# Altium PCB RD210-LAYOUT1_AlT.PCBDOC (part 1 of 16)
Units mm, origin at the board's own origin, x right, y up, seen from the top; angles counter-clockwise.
Board outline 330 x 300 mm, 6 copper layers (TOP, Mid-Layer 1, Mid-Layer 2, Mid-Layer 3, Mid-Layer 4, BOTTOM), stack 1.422 mm thick; 981 components, 463 nets, 2326 pads, 12534 vias.
Unrouted connection lines stored in the file: 6.
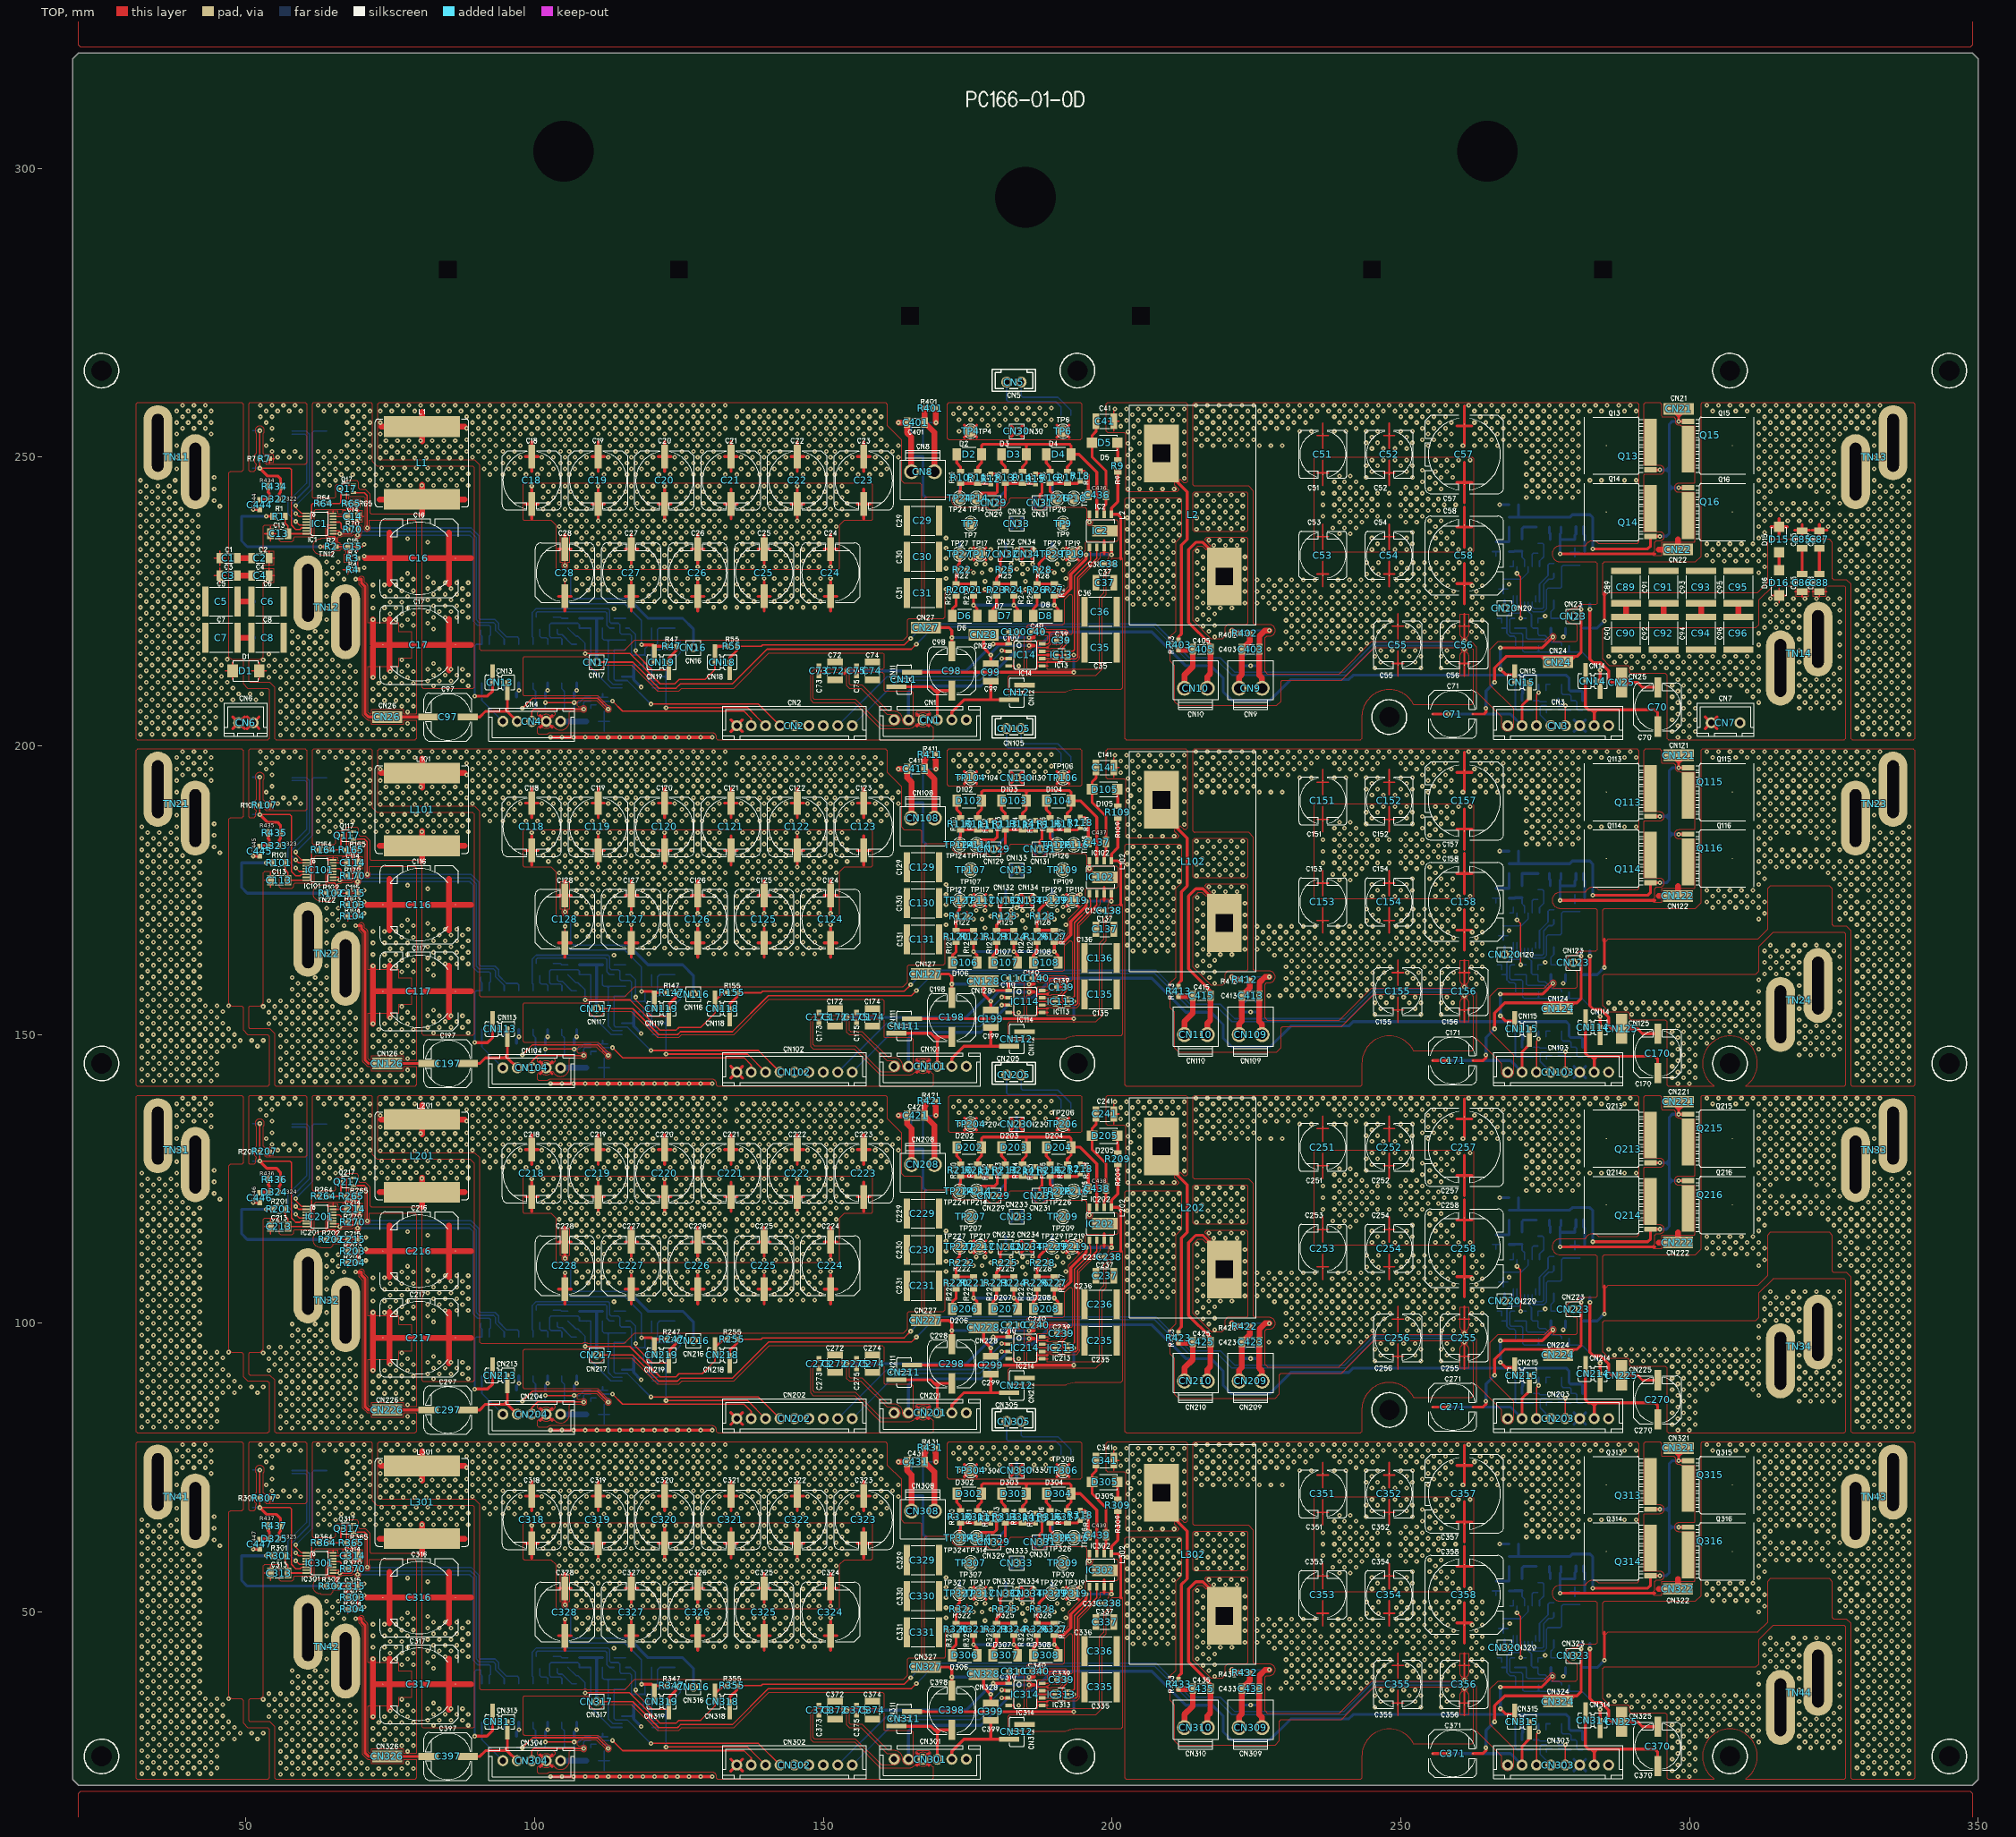
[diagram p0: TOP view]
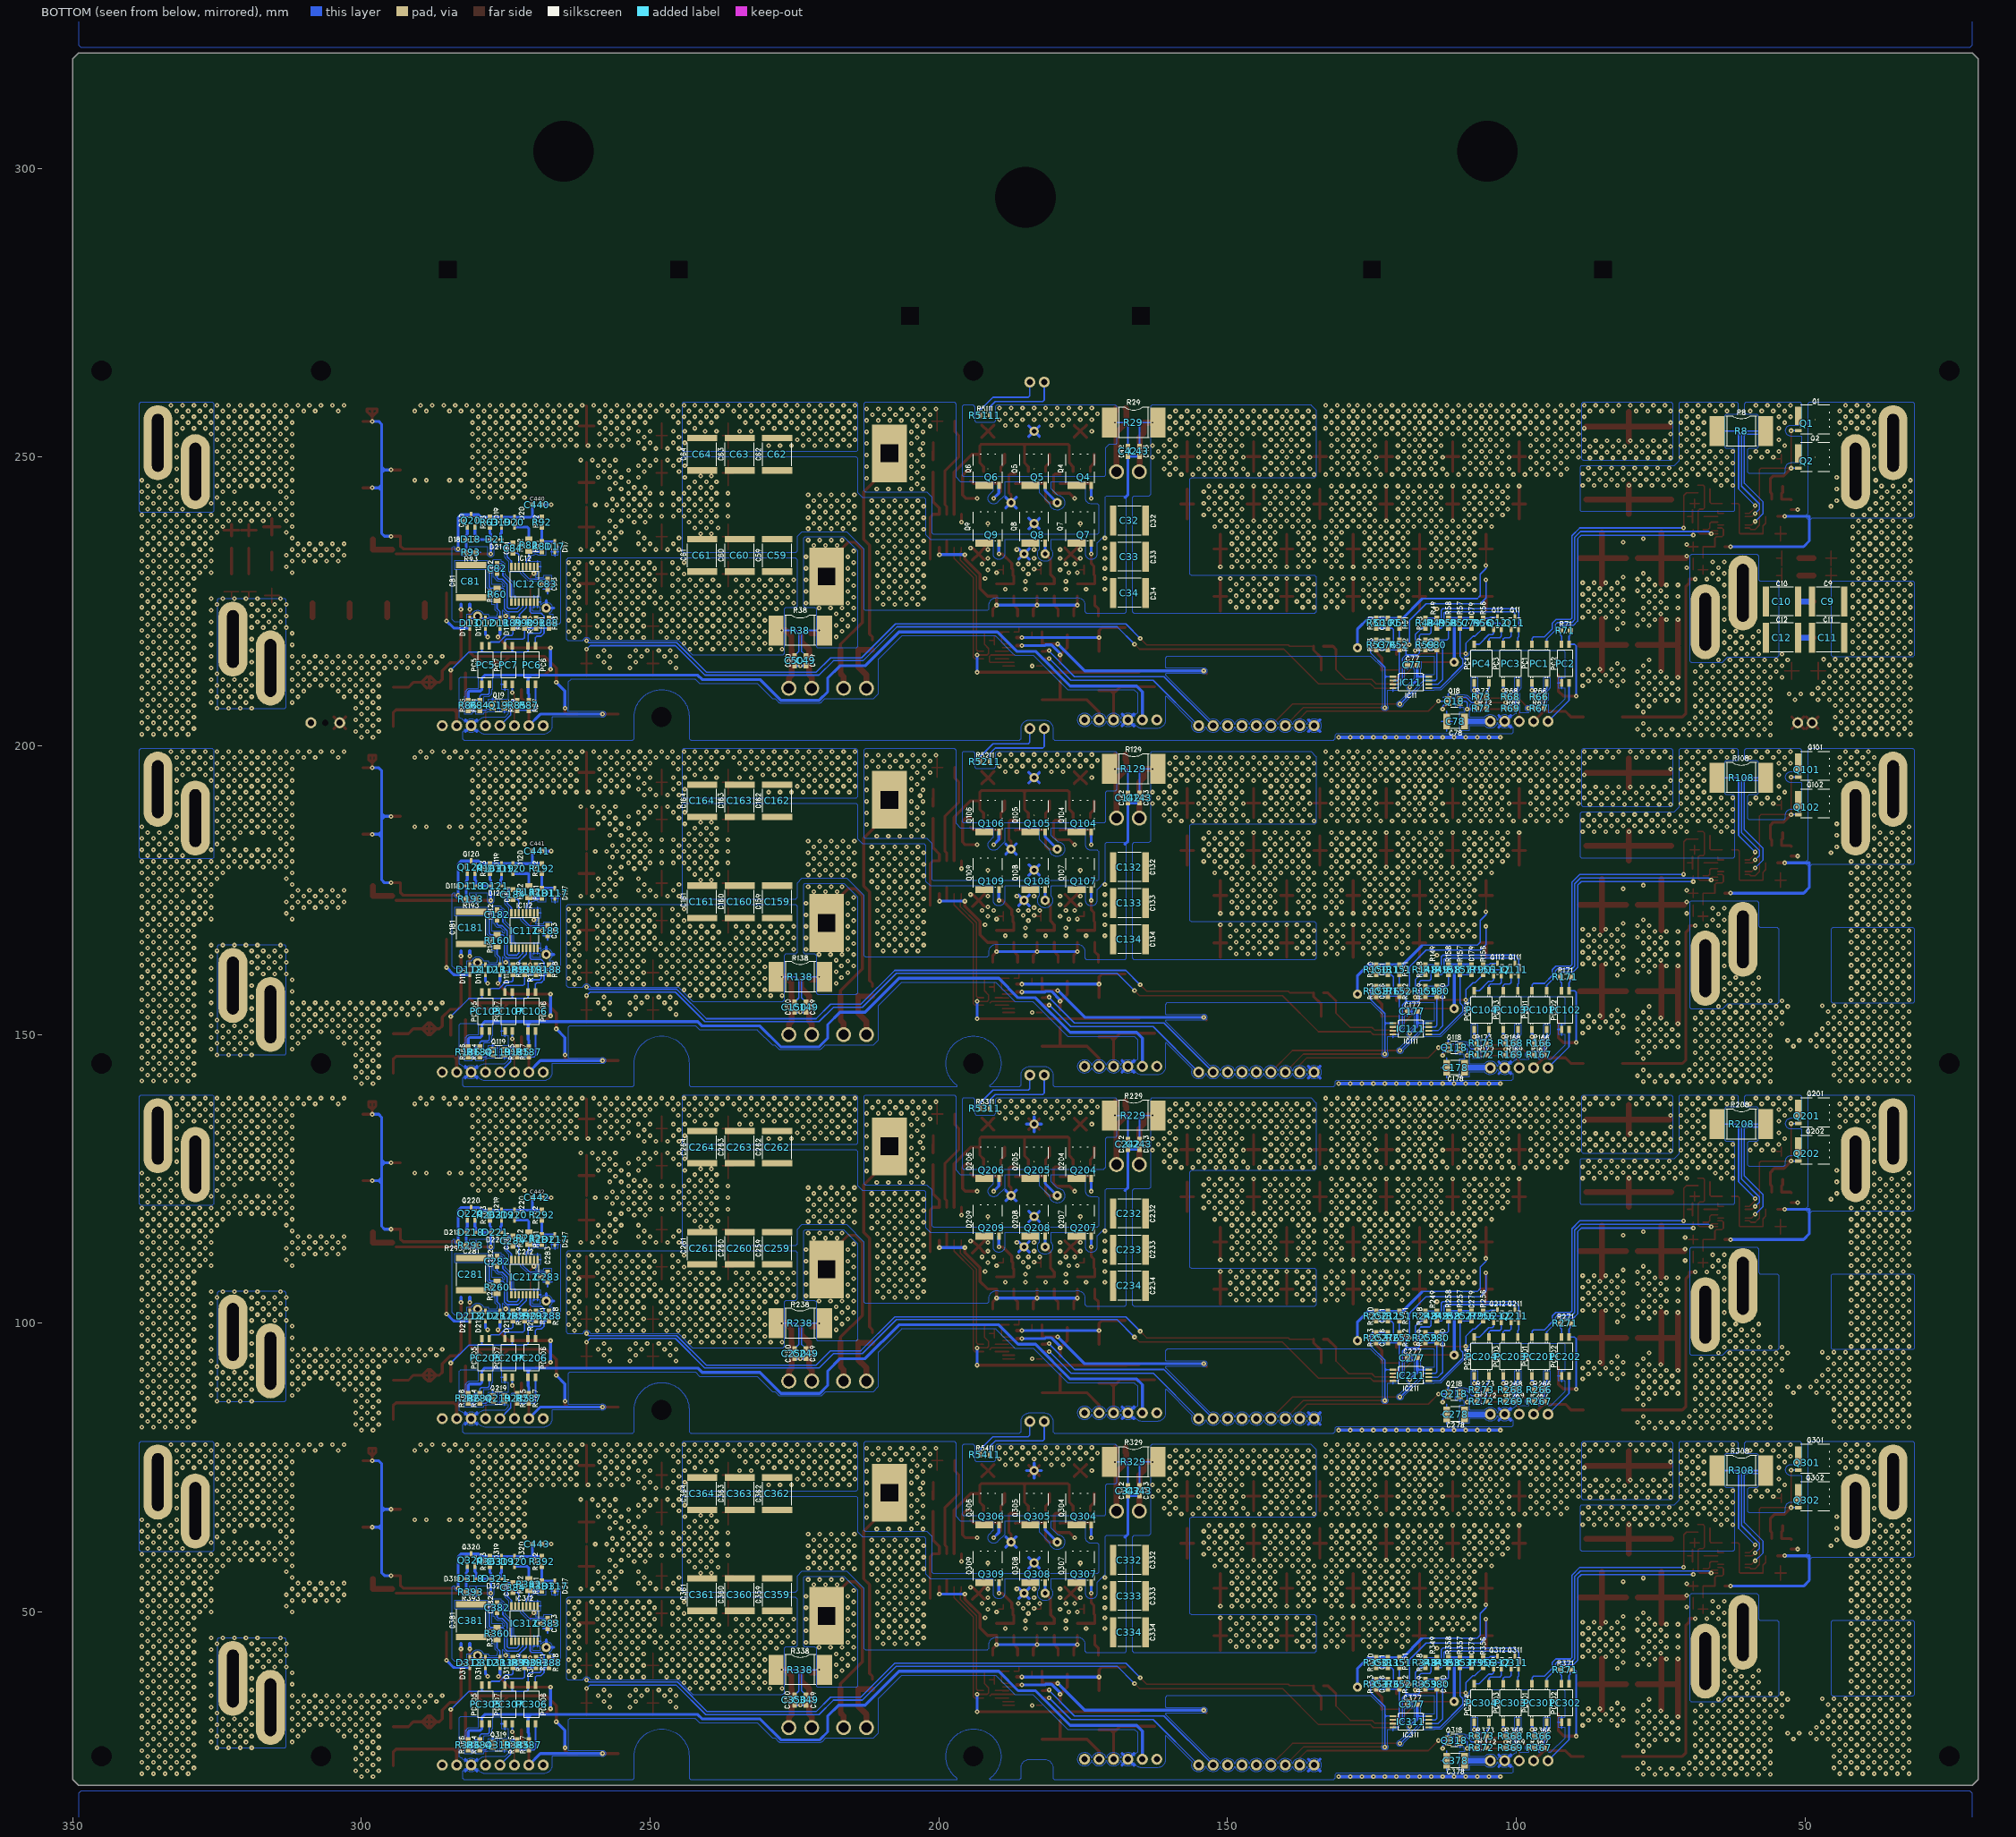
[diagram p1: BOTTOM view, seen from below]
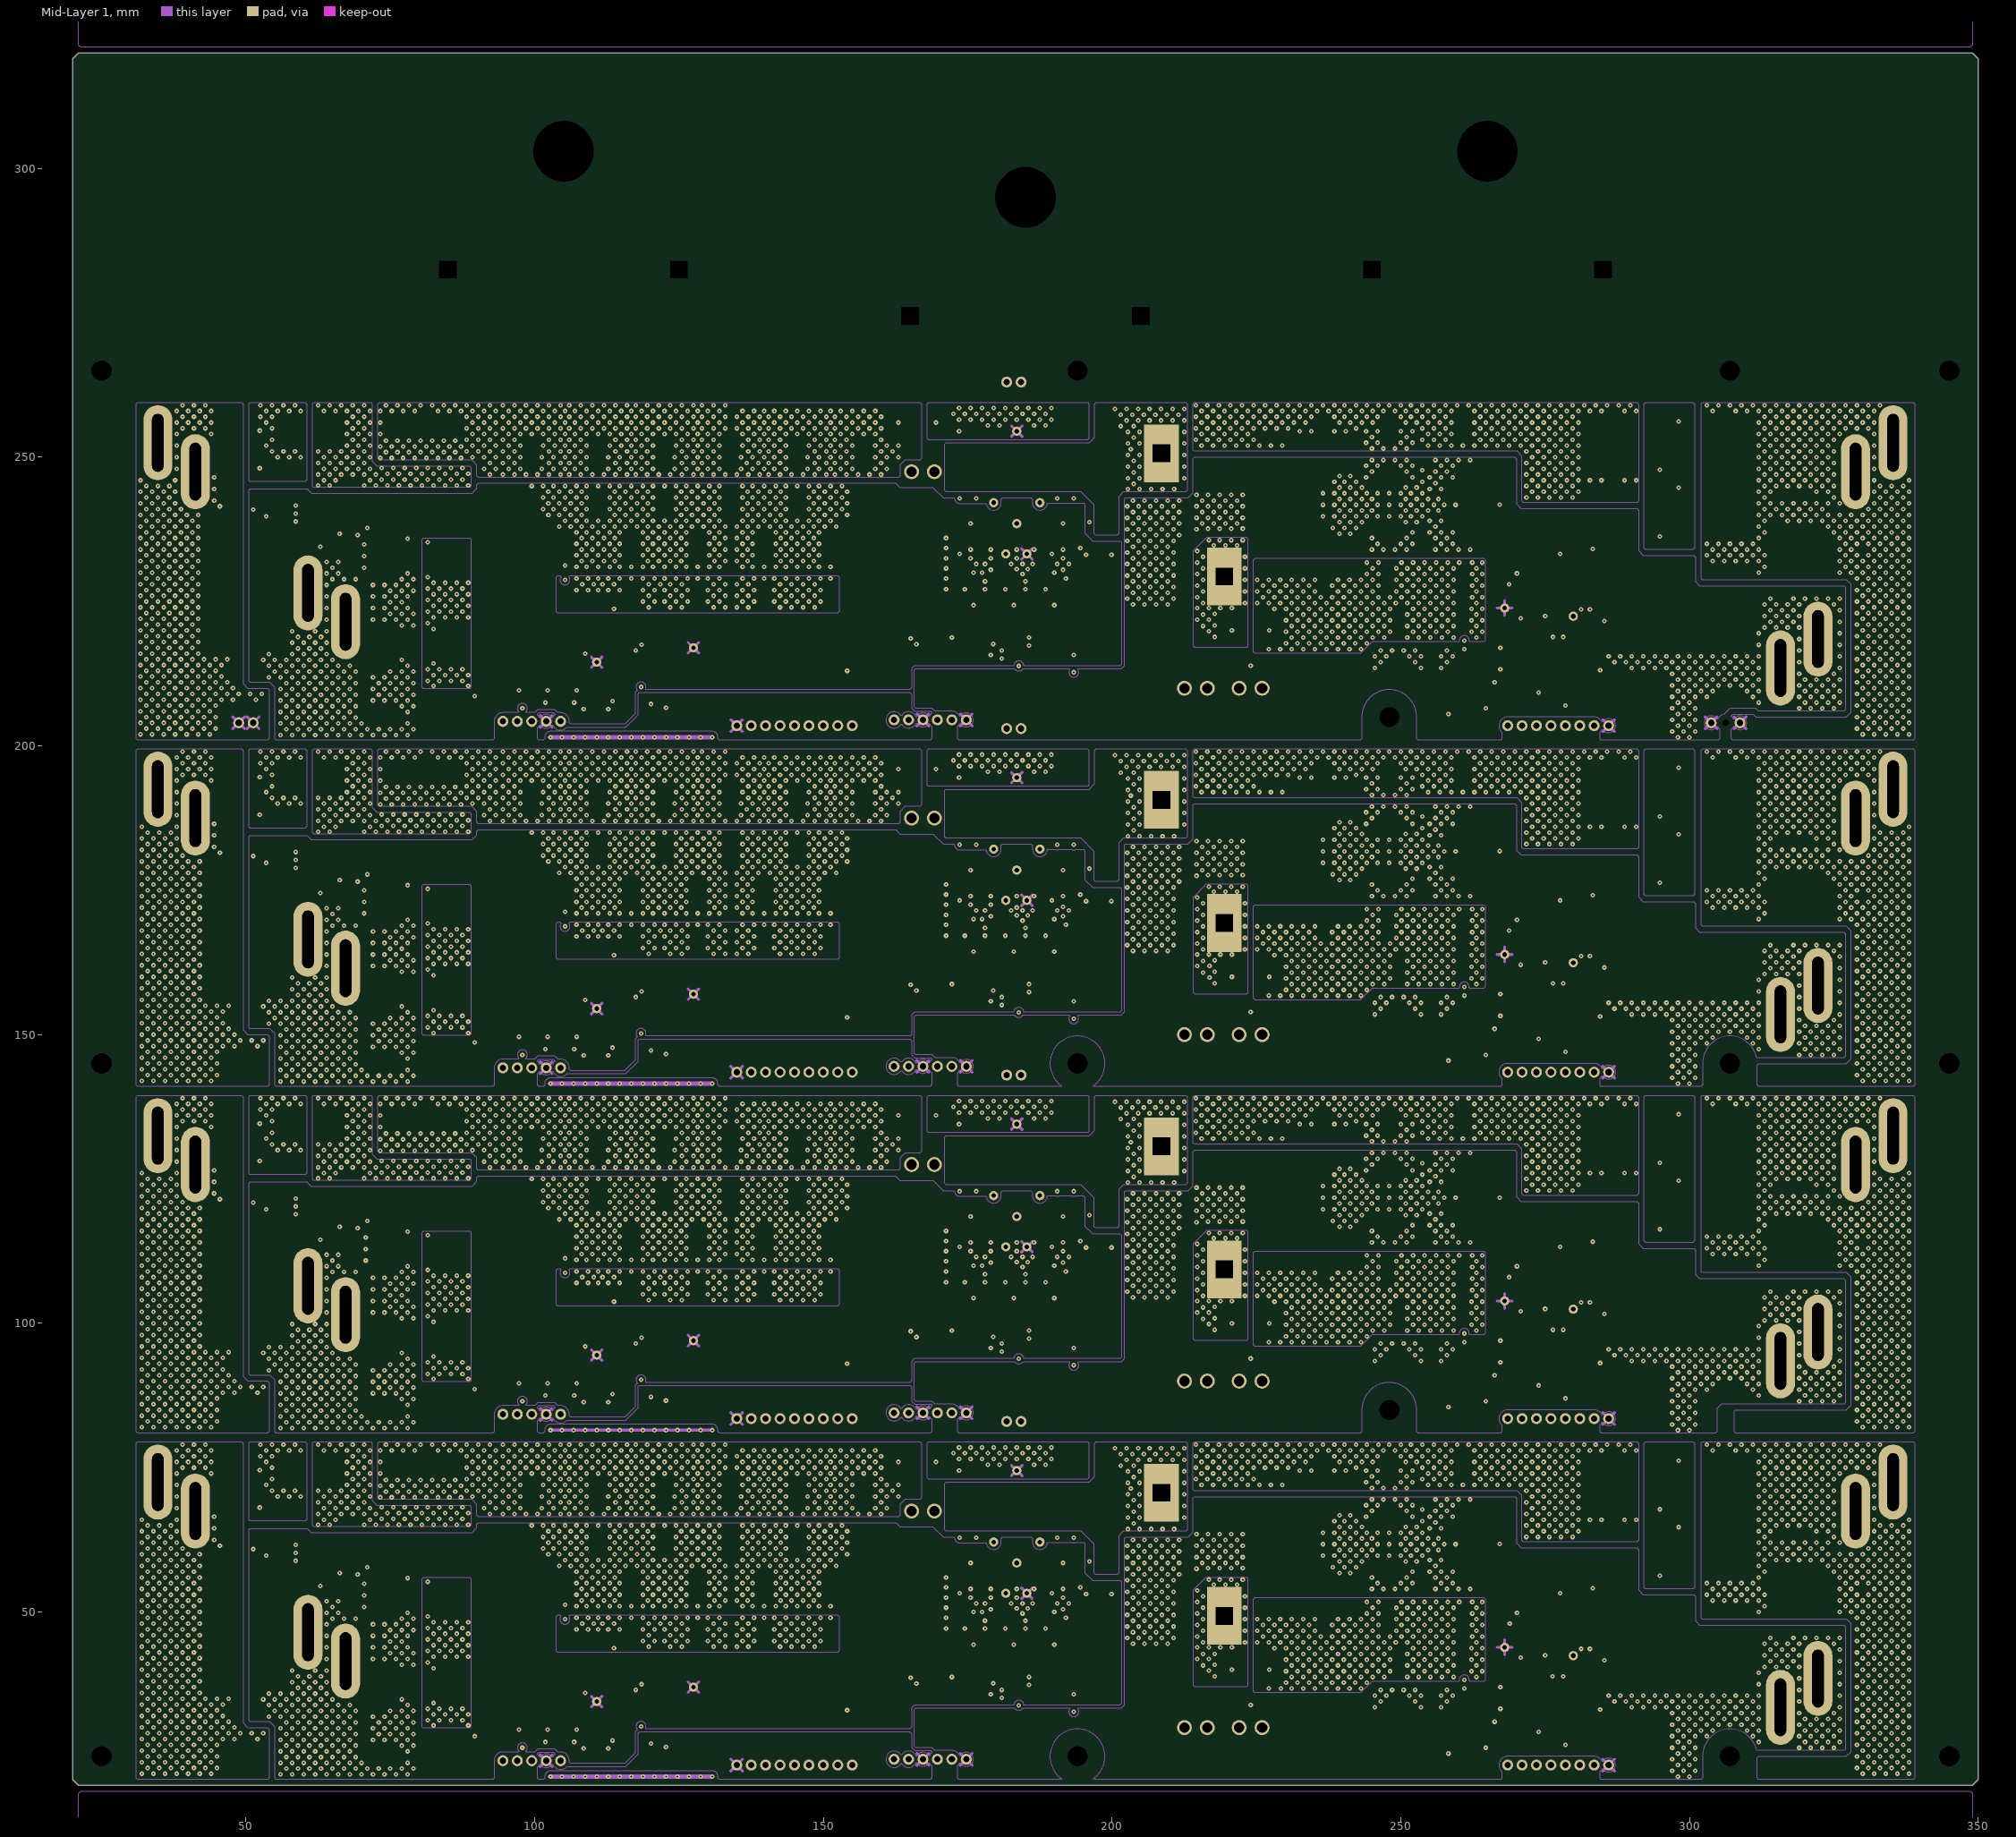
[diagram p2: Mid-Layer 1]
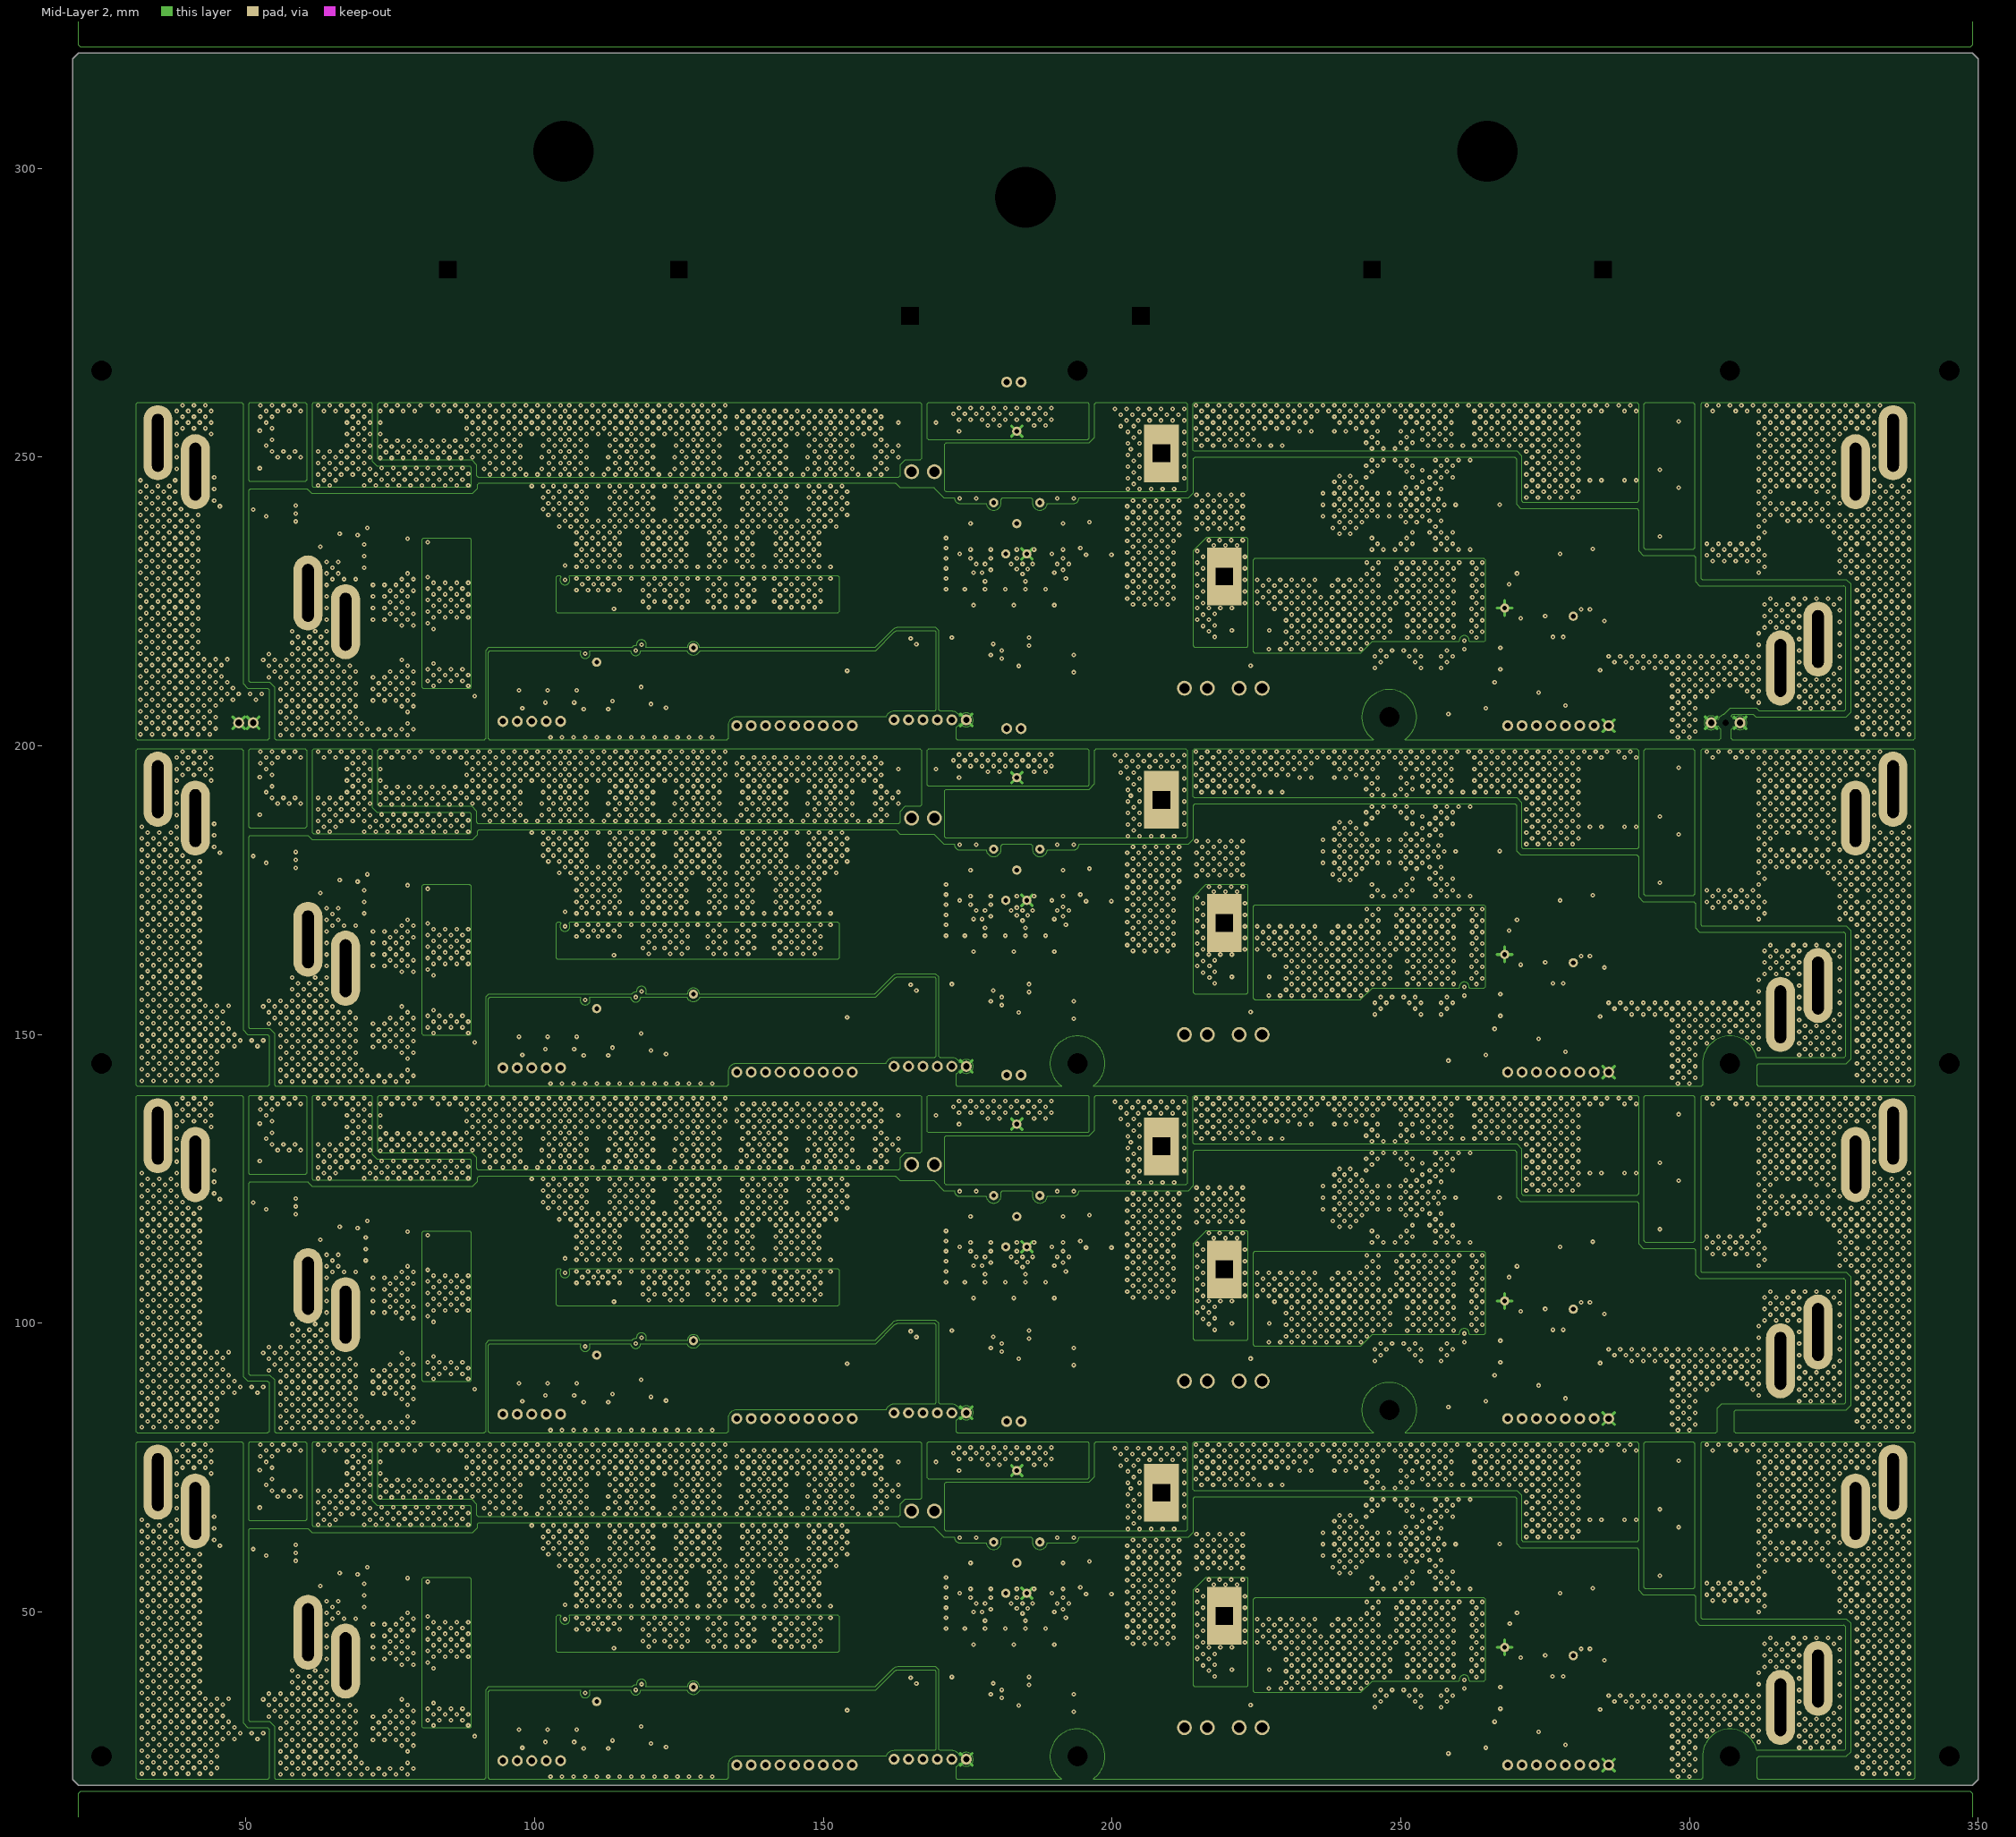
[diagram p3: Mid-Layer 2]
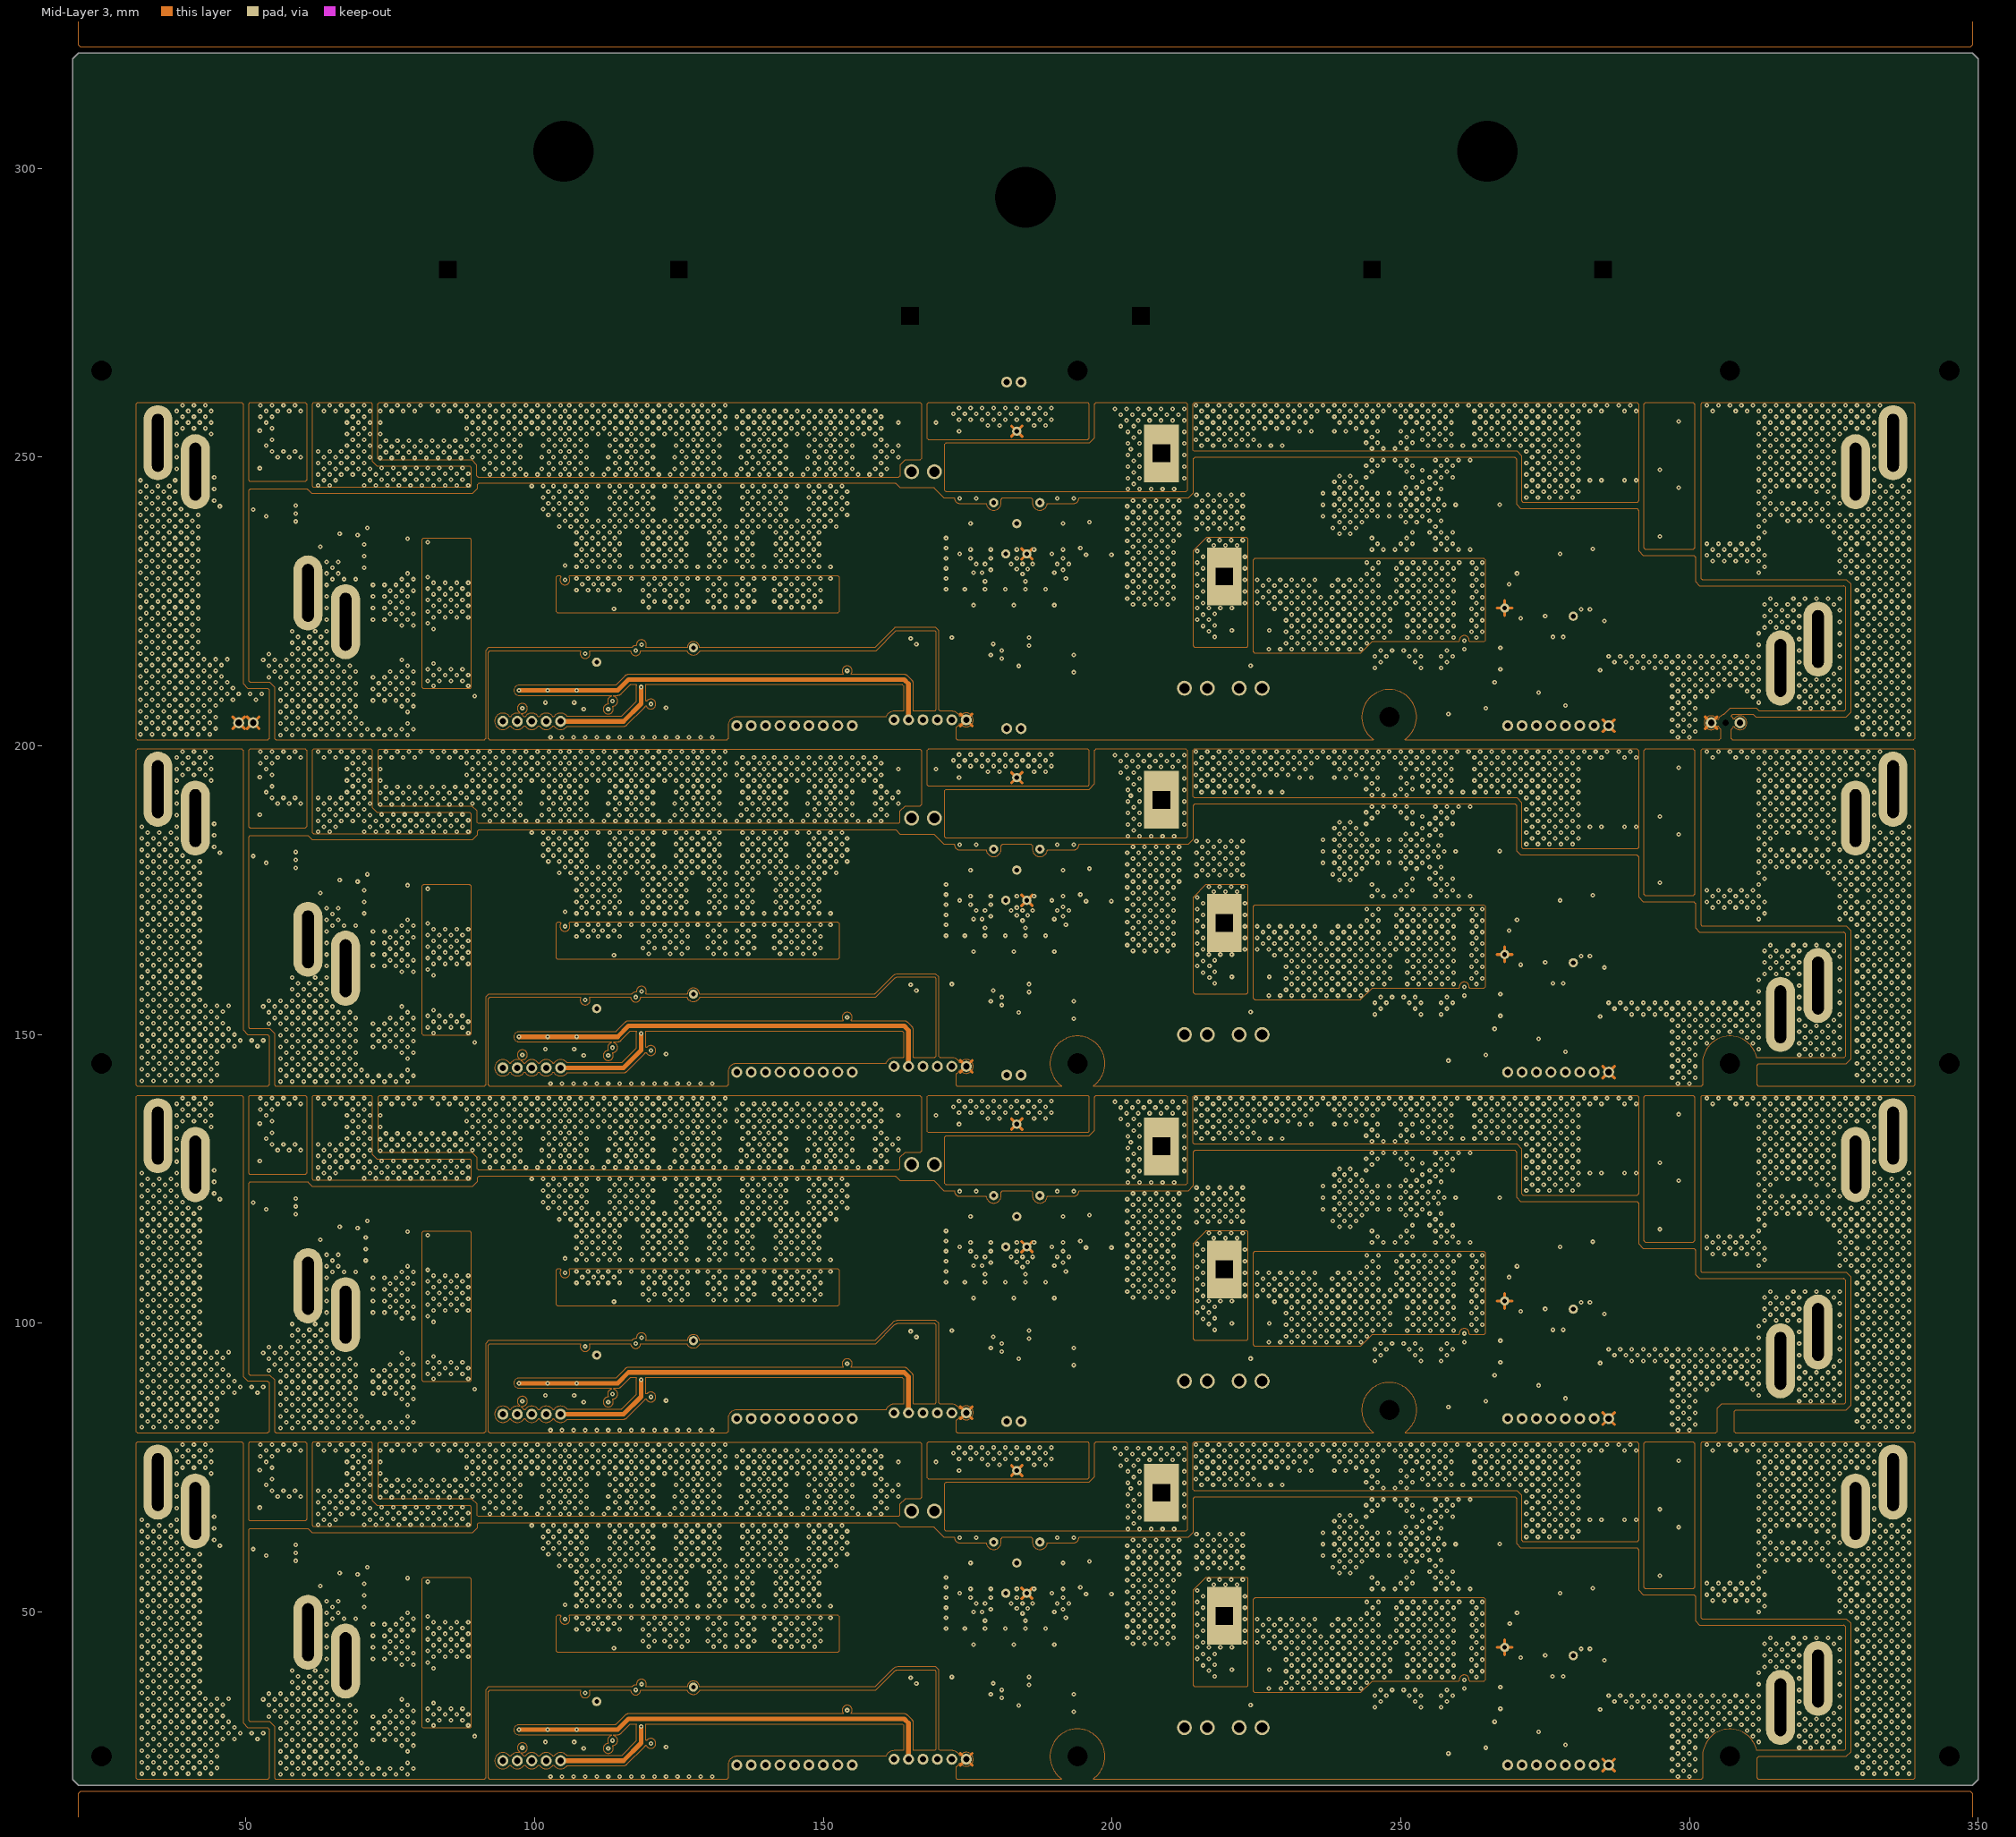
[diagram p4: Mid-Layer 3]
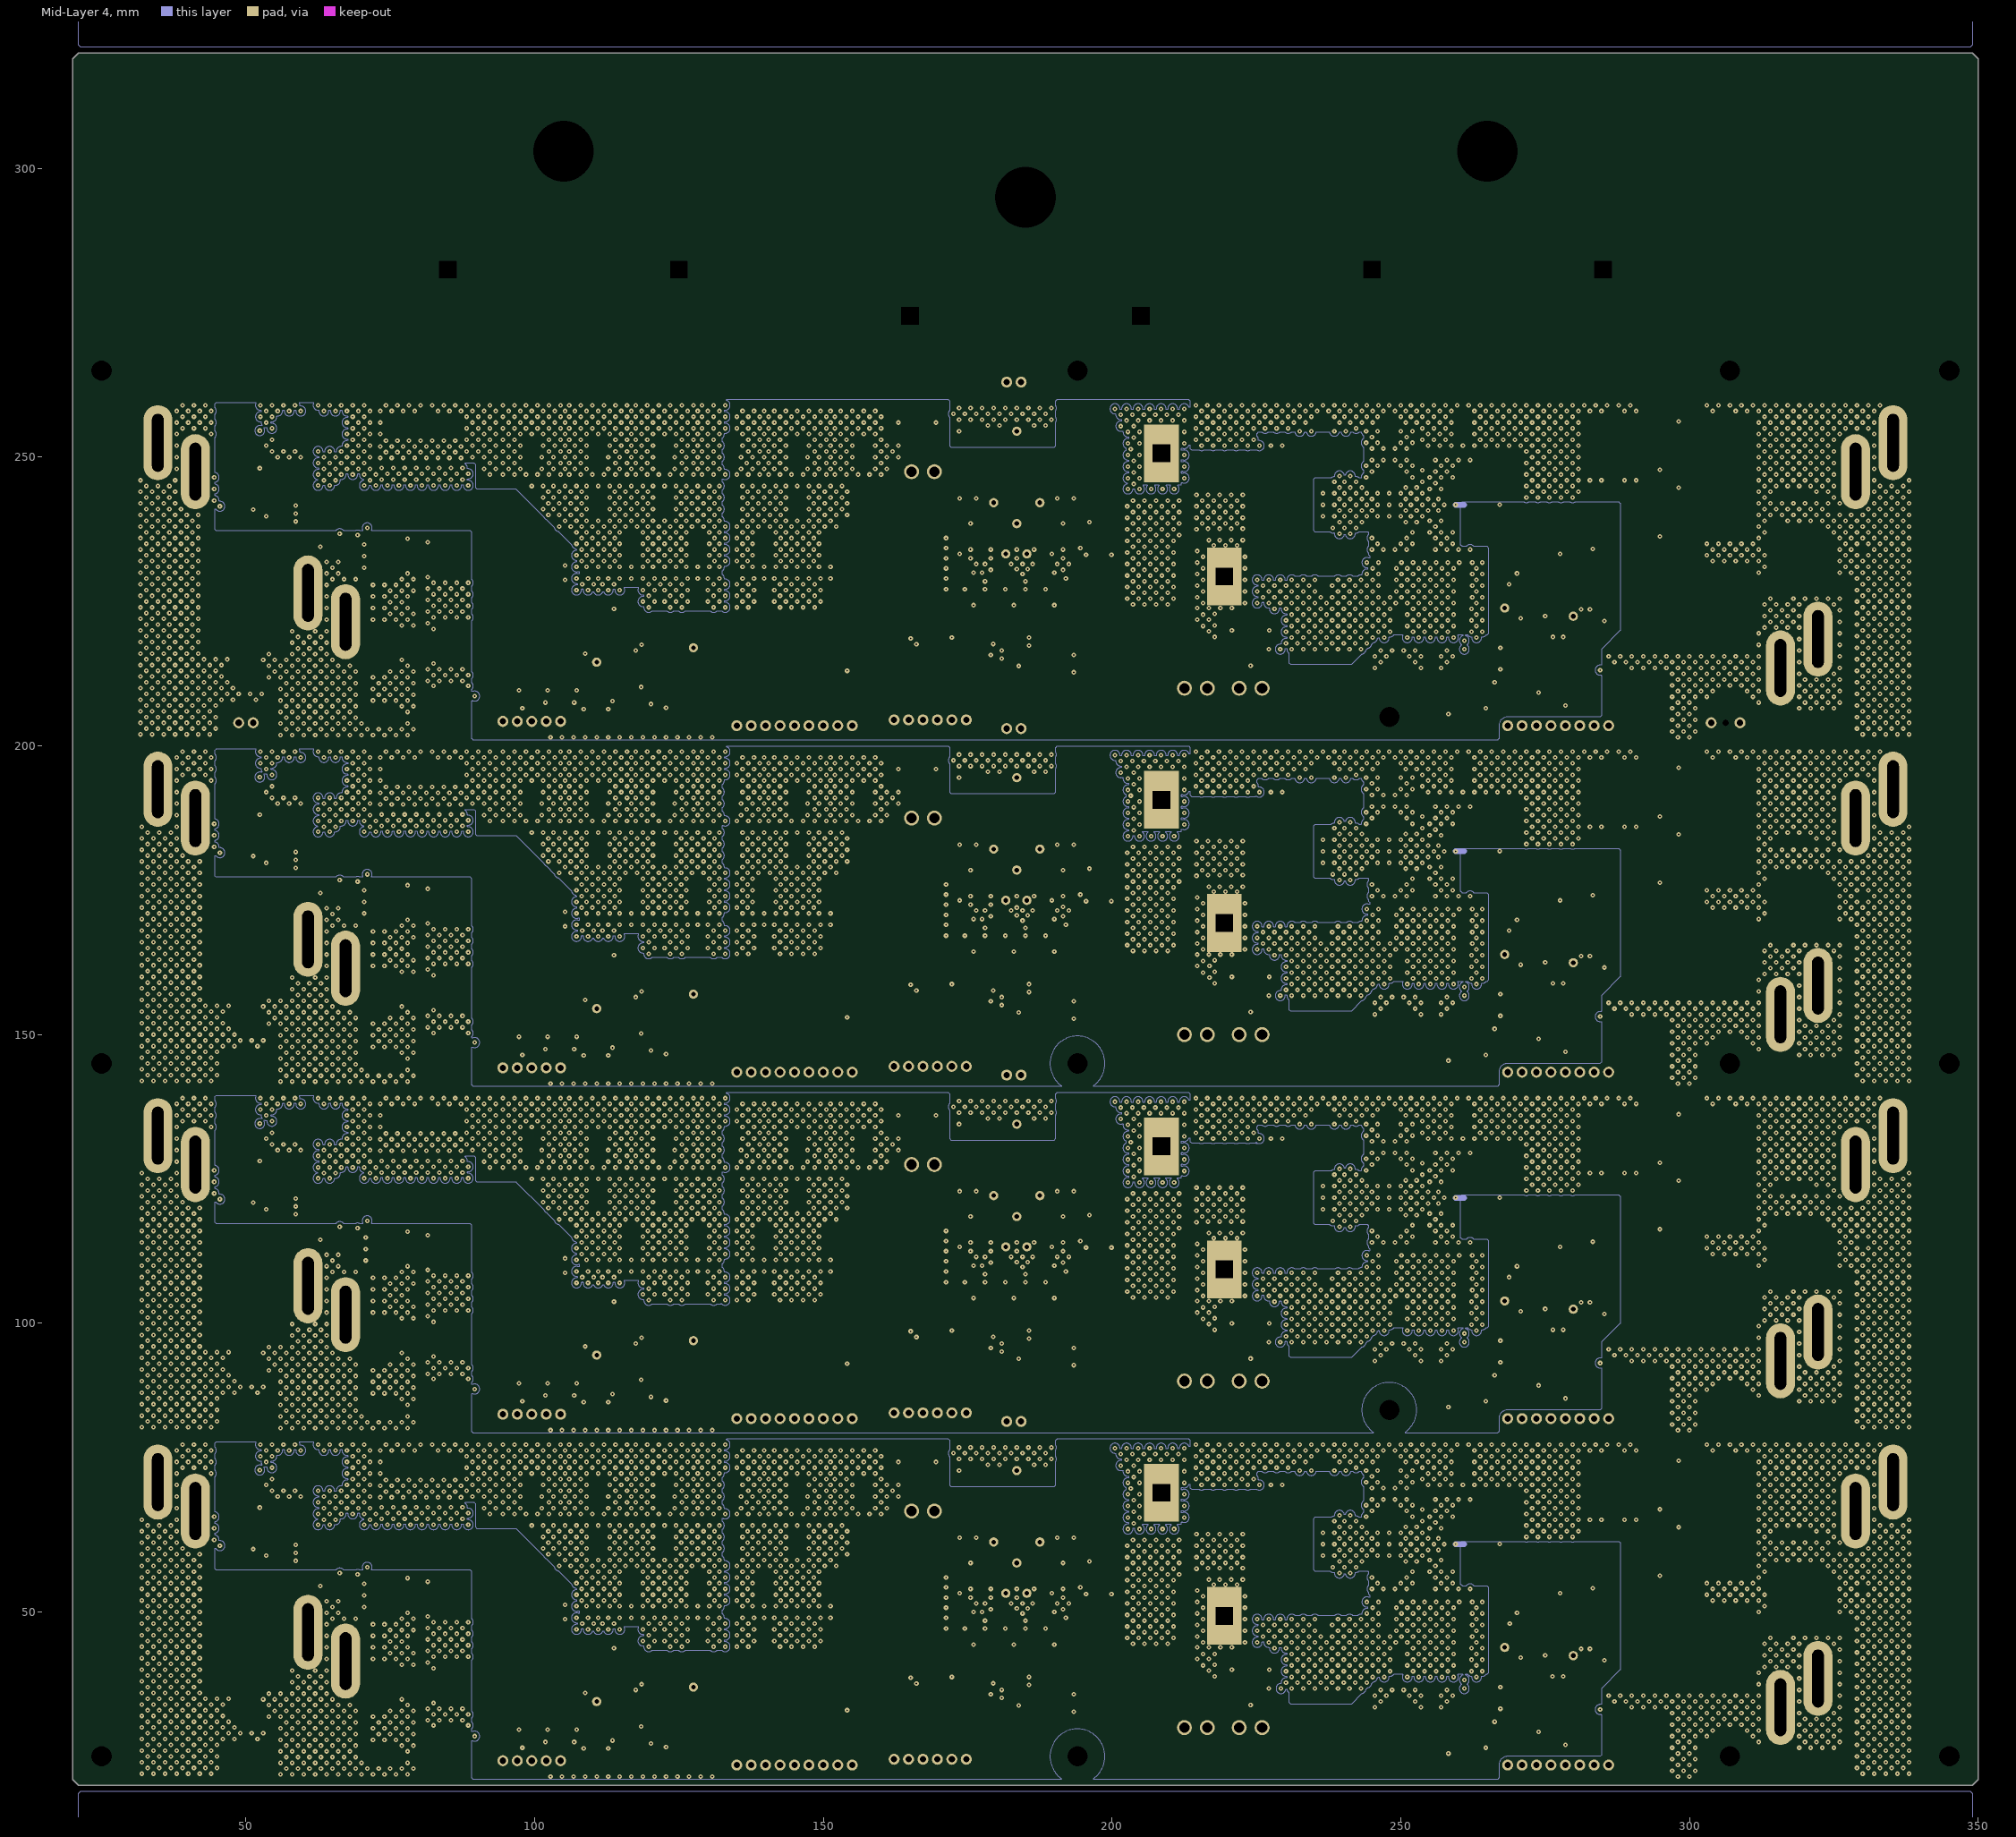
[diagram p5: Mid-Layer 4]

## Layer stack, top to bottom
Top Solder: solder mask 0.0102, Solder Resist, Dk 3.5
TOP: signal copper (thickness not stored)
Mid-Layer 1: signal copper 0.0356
Dielectric2: dielectric 0.32, FR-4, Dk 4.8
Mid-Layer 2: signal copper 0.0356
Dielectric3: dielectric 0.32, FR-4, Dk 4.8
Mid-Layer 3: signal copper 0.0356
Dielectric4: dielectric 0.32, FR-4, Dk 4.8
Mid-Layer 4: signal copper 0.0356
Dielectric5: dielectric 0.32, FR-4, Dk 4.8
BOTTOM: signal copper (thickness not stored)
Bottom Solder: solder mask 0.0102, Solder Resist, Dk 3.5

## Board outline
21,20 20,21 20,319 21,320 349,320 350,319 350,21 349,20

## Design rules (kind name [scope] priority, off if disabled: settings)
AssemblyTestPointUsage [All] p0: scope1count=1 scope1_0_kind=Board scope1_0_value=Board scope2count=1 scope2_0_kind=Board scope2_0_value=Board commentlength=0
AssemblyTestpoint [All] p0: scope1count=1 scope1_0_kind=Board scope1_0_value=Board scope2count=1 scope2_0_kind=Board scope2_0_value=Board commentlength=0
Clearance [All] p0: scope1count=1 scope1_0_kind=Board scope1_0_value=Board scope2count=1 scope2_0_kind=Board scope2_0_value=Board commentlength=0 gap=0.15
Clearance [All] p1: gap=0.15 ignorepadtopadclearanceinfootprint=TRUE except(0.3: Arc-Hole Track-Hole SMDPad-Hole THPad-Hole Via-Hole Fill-Hole Poly-Hole Region-Hole Text-Hole)
ComponentClearance [All] p0: scope1count=1 scope1_0_kind=Board scope1_0_value=Board scope2count=1 scope2_0_kind=Board scope2_0_value=Board commentlength=0 gap=0.254 collisioncheckmode=3
DiffPairsRouting [All] p0: scope1count=1 scope1_0_kind=Board scope1_0_value=Board scope2count=1 scope2_0_kind=Board scope2_0_value=Board commentlength=0
FabricationTestPointUsage [All] p0: scope1count=1 scope1_0_kind=Board scope1_0_value=Board scope2count=1 scope2_0_kind=Board scope2_0_value=Board commentlength=0 valid=0 allowmultiple=FALSE
FabricationTestpoint [All] p0: scope1count=1 scope1_0_kind=Board scope1_0_value=Board scope2count=1 scope2_0_kind=Board scope2_0_value=Board commentlength=0 side=3 testpointundercomponent=TRUE minsize=1.016 maxsize=2.54 preferedsize=1.524 minholesize=0 maxholesize=1.016 preferedholesize=0.813 testpointgrid=0.025
FanoutControl Fanout_BGA [All] p0 off: scope1count=1 scope1_0_kind=Board scope1_0_value=Board scope2count=1 scope2_0_kind=Board scope2_0_value=Board commentlength=69 // Protel DXP Scope 1 Expression Was: IsBGA   Fanout_BGA (Default Rule)
FanoutControl Fanout_LCC [All] p0 off: scope1count=1 scope1_0_kind=Board scope1_0_value=Board scope2count=1 scope2_0_kind=Board scope2_0_value=Board commentlength=69 // Protel DXP Scope 1 Expression Was: IsLCC   Fanout_LCC (Default Rule)
FanoutControl Fanout_SOIC [All] p0 off: scope1count=1 scope1_0_kind=Board scope1_0_value=Board scope2count=1 scope2_0_kind=Board scope2_0_value=Board commentlength=71 // Protel DXP Scope 1 Expression Was: IsSOIC   Fanout_SOIC (Default Rule)
FanoutControl Fanout_Small [All] p0 off: scope1count=1 scope1_0_kind=Board scope1_0_value=Board scope2count=1 scope2_0_kind=Board scope2_0_value=Board commentlength=84 // Protel DXP Scope 1 Expression Was: (CompPinCount < 5)   Fanout_Small (Default Rule)
FanoutControl Fanout_Default [All] p0: scope1count=1 scope1_0_kind=Board scope1_0_value=Board scope2count=1 scope2_0_kind=Board scope2_0_value=Board commentlength=30 // Fanout_Default (Default Rule)
Height [All] p0: scope1count=1 scope1_0_kind=Board scope1_0_value=Board scope2count=1 scope2_0_kind=Board scope2_0_value=Board commentlength=0
HoleSize [All] p0: scope1count=1 scope1_0_kind=Board scope1_0_value=Board scope2count=1 scope2_0_kind=Board scope2_0_value=Board commentlength=0 absolutevalues=TRUE maxlimit=100 minlimit=0.001 maxpercent=80.000 minpercent=20.000
HoleSize [All] p1: absolutevalues=TRUE maxlimit=100 minlimit=0.001 maxpercent=80.000 minpercent=20.000
HoleToHoleClearance [All] p0: scope1count=1 scope1_0_kind=Board scope1_0_value=Board scope2count=1 scope2_0_kind=Board scope2_0_value=Board commentlength=0
HoleToHoleClearance [All] p1: gap=0.4 allowstackedmicrovias=FALSE
LayerPairs [All] p0: scope1count=1 scope1_0_kind=Board scope1_0_value=Board scope2count=1 scope2_0_kind=Board scope2_0_value=Board commentlength=0 enforce=TRUE
MinimumSolderMaskSliver [All] p0: scope1count=1 scope1_0_kind=Board scope1_0_value=Board scope2count=1 scope2_0_kind=Board scope2_0_value=Board commentlength=0
MinimumSolderMaskSliver [All] p1: minsoldermaskwidth=0.1
NetAntennae [All] p0: scope1count=1 scope1_0_kind=Board scope1_0_value=Board scope2count=1 scope2_0_kind=Board scope2_0_value=Board commentlength=0
NetAntennae [All] p1: netantennaetolerance=100
PasteMaskExpansion [All] p0: scope1count=1 scope1_0_kind=Board scope1_0_value=Board scope2count=1 scope2_0_kind=Board scope2_0_value=Board commentlength=0 expansion=0
PlaneClearance [All] p0: scope1count=1 scope1_0_kind=Board scope1_0_value=Board scope2count=1 scope2_0_kind=Board scope2_0_value=Board commentlength=0 clearance=0.001
PlaneClearance [All] p1: clearance=0.001
PlaneConnect [All] p0: scope1count=1 scope1_0_kind=Board scope1_0_value=Board scope2count=1 scope2_0_kind=Board scope2_0_value=Board commentlength=0 planeconnectstyle=Direct reliefexpansion=0.508 reliefentries=4 reliefconductorwidth=0.254 reliefairgap=0.254
PlaneConnect [All] p1: planeconnectstyle=Direct reliefexpansion=0.508 reliefentries=4 reliefconductorwidth=0.254 reliefairgap=0.254
PolygonConnect [All] p0: scope1count=1 scope1_0_kind=Board scope1_0_value=Board scope2count=1 scope2_0_kind=Board scope2_0_value=Board commentlength=0 connectstyle=Direct reliefconductorwidth=0.254 reliefentries=4 polygonreliefangle="90 Angle"
PolygonConnect [All] p1: connectstyle=Direct reliefconductorwidth=0.254 reliefentries=4 polygonreliefangle="90 Angle" airgapwidth=0.254
RoutingCorners [All] p0: scope1count=1 scope1_0_kind=Board scope1_0_value=Board scope2count=1 scope2_0_kind=Board scope2_0_value=Board commentlength=0 cornerstyle=45-Degree minsetback=2.54 maxsetback=2.54
RoutingLayers [All] p0: scope1count=1 scope1_0_kind=Board scope1_0_value=Board scope2count=1 scope2_0_kind=Board scope2_0_value=Board commentlength=0 top layer=Automatic mid layer 1=Automatic mid layer 2=Automatic mid layer 3=Automatic mid layer 4=Automatic bottom layer=Automatic
RoutingPriority [All] p0: scope1count=1 scope1_0_kind=Board scope1_0_value=Board scope2count=1 scope2_0_kind=Board scope2_0_value=Board commentlength=0
RoutingTopology [All] p0: scope1count=1 scope1_0_kind=Board scope1_0_value=Board scope2count=1 scope2_0_kind=Board scope2_0_value=Board commentlength=0 topology=Shortest
RoutingVias [All] p0: scope1count=1 scope1_0_kind=Board scope1_0_value=Board scope2count=1 scope2_0_kind=Board scope2_0_value=Board commentlength=0 holewidth=0.1 width=0.1 viastyle="Through Hole" minholewidth=0.001 minwidth=0.001 maxholewidth=100 maxwidth=100
RoutingVias [All] p1: holewidth=0.1 width=0.1 viastyle="Through Hole" minholewidth=0.001 minwidth=0.001 maxholewidth=100 maxwidth=100
ShortCircuit [All] p0: scope1count=1 scope1_0_kind=Board scope1_0_value=Board scope2count=1 scope2_0_kind=Board scope2_0_value=Board commentlength=0 allowed=FALSE
SilkToBoardRegionClearance [All] p0: scope1count=1 scope1_0_kind=Board scope1_0_value=Board scope2count=1 scope2_0_kind=Board scope2_0_value=Board commentlength=0
SilkToSilkClearance [All] p0: scope1count=1 scope1_0_kind=Board scope1_0_value=Board scope2count=1 scope2_0_kind=Board scope2_0_value=Board commentlength=0
SilkToSilkClearance [All] p1: silktosilkclearance=0.001
SilkToSolderMaskClearance [All] p0 off: scope1count=1 scope1_0_kind=Board scope1_0_value=Board scope2count=1 scope2_0_kind=Board scope2_0_value=Board commentlength=44 // Protel DXP Scope 1 Expression Was: IsPad
SilkToSolderMaskClearance [IsPad] p1: minsilkscreentomaskgap=0 clearancetoexposedcopper=TRUE
SolderMaskExpansion [All] p0: scope1count=1 scope1_0_kind=Board scope1_0_value=Board scope2count=1 scope2_0_kind=Board scope2_0_value=Board commentlength=0 expansion=0.001
SolderMaskExpansion [All] p1: expansion=0.001
UnRoutedNet [All] p0: scope1count=1 scope1_0_kind=Board scope1_0_value=Board scope2count=1 scope2_0_kind=Board scope2_0_value=Board commentlength=0
UnpouredPolygon [All] p0: scope1count=1 scope1_0_kind=Board scope1_0_value=Board scope2count=1 scope2_0_kind=Board scope2_0_value=Board commentlength=0
Width [All] p0: scope1count=1 scope1_0_kind=Board scope1_0_value=Board scope2count=1 scope2_0_kind=Board scope2_0_value=Board commentlength=0 maxlimit=1000 minlimit=2539.975 preferedwidth=0
Width [All] p1: maxlimit=1000 minlimit=2539.975 preferedwidth=0 toplayer_minwidth=0 midlayer1_minwidth=0 midlayer2_minwidth=0 midlayer3_minwidth=0 midlayer4_minwidth=0 bottomlayer_minwidth=0 minimp=50.000000 maximp=50.000000 favimp=50.000000
22 further rules are at their usual default settings.

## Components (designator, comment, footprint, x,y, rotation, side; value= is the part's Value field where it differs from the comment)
C1 "_CGA5L2X7R2A474K160AA_" _CGA5L2X7R2A474K160AA_ 47,232.5 r180 top
C2 "_CGA5L2X7R2A474K160AA_+1" _CGA5L2X7R2A474K160AA_+1 52.5,232.5 r180 top
C3 "_CGA5L2X7R2A474K160AA_+2" _CGA5L2X7R2A474K160AA_+2 47,229.5 r180 top
C4 "_CGA5L2X7R2A474K160AA_+3" _CGA5L2X7R2A474K160AA_+3 52.5,229.5 r180 top
C5 "S2P_CC-5.7x5x2.3-PX5.7" S2P_CC-5.7x5x2.3-PX5.7 45.75,225 r180 top
C6 "S2P_CC-5.7x5x2.3-PX5.7+1" S2P_CC-5.7x5x2.3-PX5.7+1 53.75,225 r180 top
C7 "S2P_CC-5.7x5x2.3-PX5.7+2" S2P_CC-5.7x5x2.3-PX5.7+2 45.75,218.75 r180 top
C8 "S2P_CC-5.7x5x2.3-PX5.7+3" S2P_CC-5.7x5x2.3-PX5.7+3 53.75,218.75 r180 top
C9 "S2P_CC-5.7x5x2.3-PX5.7+4" S2P_CC-5.7x5x2.3-PX5.7+4 46,225 r0 bottom
C10 "S2P_CC-5.7x5x2.3-PX5.7+5" S2P_CC-5.7x5x2.3-PX5.7+5 54,225 r0 bottom
C11 "S2P_CC-5.7x5x2.3-PX5.7+6" S2P_CC-5.7x5x2.3-PX5.7+6 46,218.75 r0 bottom
C12 "S2P_CC-5.7x5x2.3-PX5.7+7" S2P_CC-5.7x5x2.3-PX5.7+7 54,218.75 r0 bottom
C13 "_CGA5L2X7R2A104K160AA_" _CGA5L2X7R2A104K160AA_ 55.75,236.75 r0 top
C14 "S2P_CC-2x1.25x1.25-PX2" S2P_CC-2x1.25x1.25-PX2 68.5,239.75 r0 top
C15 "S2P_CC-1.6x0.8x0.8-PX1.6+73" S2P_CC-1.6x0.8x0.8-PX1.6+73 68.5,234.5 r180 top
C16 "_UCZ1K151MNS1MS_+1" _UCZ1K151MNS1MS_+1 80,232.5 r180 top
C17 "_UCZ1K151MNS1MS_" _UCZ1K151MNS1MS_ 80,217.5 r180 top
C18 "S2P_CE-10.3x10.3x12.6-PX11" S2P_CE-10.3x10.3x12.6-PX11 99.5,246 r270 top
C19 "S2P_CE-10.3x10.3x12.6-PX11+1" S2P_CE-10.3x10.3x12.6-PX11+1 111,246 r270 top
C20 "S2P_CE-10.3x10.3x12.6-PX11+2" S2P_CE-10.3x10.3x12.6-PX11+2 122.5,246 r270 top
C21 "S2P_CE-10.3x10.3x12.6-PX11+3" S2P_CE-10.3x10.3x12.6-PX11+3 134,246 r270 top
C22 "S2P_CE-10.3x10.3x12.6-PX11+4" S2P_CE-10.3x10.3x12.6-PX11+4 145.5,246 r270 top
C23 "S2P_CE-10.3x10.3x12.6-PX11+5" S2P_CE-10.3x10.3x12.6-PX11+5 157,246 r270 top
C24 "S2P_CE-10.3x10.3x12.6-PX11+6" S2P_CE-10.3x10.3x12.6-PX11+6 151.25,230 r90 top
C25 "S2P_CE-10.3x10.3x12.6-PX11+9" S2P_CE-10.3x10.3x12.6-PX11+9 139.75,230 r90 top
C26 "S2P_CE-10.3x10.3x12.6-PX11+10" S2P_CE-10.3x10.3x12.6-PX11+10 128.25,230 r90 top
C27 "S2P_CE-10.3x10.3x12.6-PX11+7" S2P_CE-10.3x10.3x12.6-PX11+7 116.75,230 r90 top
C28 "S2P_CE-10.3x10.3x12.6-PX11+8" S2P_CE-10.3x10.3x12.6-PX11+8 105.25,230 r90 top
C29 "S2P_CC-5.7x5x2.3-PX5.7+10" S2P_CC-5.7x5x2.3-PX5.7+10 167.25,239 r180 top
C30 "S2P_CC-5.7x5x2.3-PX5.7+20" S2P_CC-5.7x5x2.3-PX5.7+20 167.25,232.75 r180 top
C31 "S2P_CC-5.7x5x2.3-PX5.7+21" S2P_CC-5.7x5x2.3-PX5.7+21 167.25,226.5 r180 top
C32 "S2P_CC-5.7x5x2.3-PX5.7+61" S2P_CC-5.7x5x2.3-PX5.7+61 167,239 r0 bottom
C33 "S2P_CC-5.7x5x2.3-PX5.7+62" S2P_CC-5.7x5x2.3-PX5.7+62 167,232.75 r0 bottom
C34 "S2P_CC-5.7x5x2.3-PX5.7+63" S2P_CC-5.7x5x2.3-PX5.7+63 167,226.5 r0 bottom
C35 "S2P_CC-5.7x5x2.3-PX5.7+8" S2P_CC-5.7x5x2.3-PX5.7+8 198,217 r0 top
C36 "S2P_CC-5.7x5x2.3-PX5.7+9" S2P_CC-5.7x5x2.3-PX5.7+9 198,223.25 r0 top
C37 "_CGA6M3X7R1H225K200AB_" _CGA6M3X7R1H225K200AB_ 198.75,228.25 r180 top
C38 "S2P_CC-1.6x0.8x0.8-PX1.6" S2P_CC-1.6x0.8x0.8-PX1.6#1 199.5,231.5 r180 top
C39 "S2P_CC-1.6x0.8x0.8-PX1.6+51" S2P_CC-1.6x0.8x0.8-PX1.6+51 191.25,218.25 r0 top
C40 "S2P_CC-1.6x0.8x0.8-PX1.6+50" S2P_CC-1.6x0.8x0.8-PX1.6+50 187,219.75 r0 top
C41 "_CGA6M3X7R1H225K200AB_+1" _CGA6M3X7R1H225K200AB_+1 198.75,256.25 r0 top
C42 "S2P_CC-1.6x0.8x0.8-PX1.6+1" S2P_CC-1.6x0.8x0.8-PX1.6+1 167.25,251 r90 bottom
C43 "S2P_CC-1.6x0.8x0.8-PX1.6+2" S2P_CC-1.6x0.8x0.8-PX1.6+2 165.25,251 r90 bottom
C49 "S2P_CC-1.6x0.8x0.8-PX1.6+69" S2P_CC-1.6x0.8x0.8-PX1.6+69 223,214.75 r90 bottom
C50 "S2P_CC-1.6x0.8x0.8-PX1.6+68" S2P_CC-1.6x0.8x0.8-PX1.6+68 225,214.75 r90 bottom
C51 "_PCV1J390MCL2GS_" _PCV1J390MCL2GS_ 236.5,250.5 r270 top
C52 "_PCV1J390MCL2GS_+1" _PCV1J390MCL2GS_+1 248,250.5 r270 top
C53 "_PCV1J390MCL2GS_+2" _PCV1J390MCL2GS_+2 236.5,233 r90 top
C54 "_PCV1J390MCL2GS_+3" _PCV1J390MCL2GS_+3 248,233 r90 top
C55 "_PCV1J390MCL2GS_+4" _PCV1J390MCL2GS_+4 249.5,217.5 r270 top
C56 "_PCV1J390MCL2GS_+5" _PCV1J390MCL2GS_+5 261,217.5 r270 top
C57 "_UCZ1J151MNQ1MS_" _UCZ1J151MNQ1MS_ 261,250.5 r270 top
C58 "_UCZ1J151MNQ1MS_+1" _UCZ1J151MNQ1MS_+1 261,233 r90 top
C59 "S2P_CC-5.7x5x2.3-PX5.7+67" S2P_CC-5.7x5x2.3-PX5.7+67 228,233 r90 bottom
C60 "S2P_CC-5.7x5x2.3-PX5.7+65" S2P_CC-5.7x5x2.3-PX5.7+65 234.5,233 r90 bottom
C61 "S2P_CC-5.7x5x2.3-PX5.7+66" S2P_CC-5.7x5x2.3-PX5.7+66 241,233 r90 bottom
C62 "S2P_CC-5.7x5x2.3-PX5.7+68" S2P_CC-5.7x5x2.3-PX5.7+68 228,250.5 r270 bottom
C63 "S2P_CC-5.7x5x2.3-PX5.7+64" S2P_CC-5.7x5x2.3-PX5.7+64 234.5,250.5 r270 bottom
C64 "S2P_CC-5.7x5x2.3-PX5.7+69" S2P_CC-5.7x5x2.3-PX5.7+69 241,250.5 r270 bottom
C70 "_UCZ1A221MCL1GS_+7" _UCZ1A221MCL1GS_+7 294.5,206.75 r90 top
C71 "_UCZ1C221MCL1GS_" _UCZ1C221MCL1GS_ 259,205.5 r0 top
C72 "_CGA6M3X7R1H225K200AB_+14" _CGA6M3X7R1H225K200AB_+14 152,213 r90 top
C73 "S2P_CC-1.6x0.8x0.8-PX1.6+6" S2P_CC-1.6x0.8x0.8-PX1.6+6 149.25,213 r90 top
C74 "_CGA6M3X7R1H225K200AB_+15" _CGA6M3X7R1H225K200AB_+15 158.5,213 r90 top
C75 "S2P_CC-1.6x0.8x0.8-PX1.6+7" S2P_CC-1.6x0.8x0.8-PX1.6+7 155.75,213 r90 top
C76 "S2P_CC-1.6x0.8x0.8-PX1.6+36" S2P_CC-1.6x0.8x0.8-PX1.6+36 122.25,217.5 r270 bottom
C77 "S2P_CC-1.6x0.8x0.8-PX1.6+3" S2P_CC-1.6x0.8x0.8-PX1.6+3 118,214 r0 bottom
C78 "_CGA6M3X7R1H225K200AB_+23" _CGA6M3X7R1H225K200AB_+23 110.5,204.25 r0 bottom
C79 "S2P_CC-1.6x0.8x0.8-PX1.6+44" S2P_CC-1.6x0.8x0.8-PX1.6+44 107.75,221.25 r90 bottom
C80 "S2P_CC-1.6x0.8x0.8-PX1.6+37" S2P_CC-1.6x0.8x0.8-PX1.6+37 113.75,217.5 r90 bottom
C81 "S2P_CC-5.7x5x2.3-PX5.7+11" S2P_CC-5.7x5x2.3-PX5.7+11 281,228.5 r270 bottom
C82 "S2P_CC-1.6x0.8x0.8-PX1.6+4" S2P_CC-1.6x0.8x0.8-PX1.6+4 276.5,230.75 r270 bottom
C83 "S2P_CC-1.6x0.8x0.8-PX1.6+64" S2P_CC-1.6x0.8x0.8-PX1.6+64 267.75,228 r90 bottom
C84 "S2P_CC-1.6x0.8x0.8-PX1.6+5" S2P_CC-1.6x0.8x0.8-PX1.6+5 273.75,234.25 r270 bottom
C85 "_CGA5L2X7R2A474K160AA_+4" _CGA5L2X7R2A474K160AA_+4 319.5,235.75 r90 top
C86 "_CGA5L2X7R2A474K160AA_+5" _CGA5L2X7R2A474K160AA_+5 319.5,228.25 r90 top
C87 "_CGA5L2X7R2A474K160AA_+6" _CGA5L2X7R2A474K160AA_+6 322.5,235.75 r90 top
C88 "_CGA5L2X7R2A474K160AA_+7" _CGA5L2X7R2A474K160AA_+7 322.5,228.25 r90 top
C89 "S2P_CC-5.7x5x2.3-PX5.7+14" S2P_CC-5.7x5x2.3-PX5.7+14 289,227.5 r90 top
C90 "S2P_CC-5.7x5x2.3-PX5.7+15" S2P_CC-5.7x5x2.3-PX5.7+15 289,219.5 r90 top
C91 "S2P_CC-5.7x5x2.3-PX5.7+16" S2P_CC-5.7x5x2.3-PX5.7+16 295.5,227.5 r90 top
C92 "S2P_CC-5.7x5x2.3-PX5.7+17" S2P_CC-5.7x5x2.3-PX5.7+17 295.5,219.5 r90 top
C93 "S2P_CC-5.7x5x2.3-PX5.7+18" S2P_CC-5.7x5x2.3-PX5.7+18 302,227.5 r90 top
C94 "S2P_CC-5.7x5x2.3-PX5.7+19" S2P_CC-5.7x5x2.3-PX5.7+19 302,219.5 r90 top
C95 "S2P_CC-5.7x5x2.3-PX5.7+12" S2P_CC-5.7x5x2.3-PX5.7+12 308.5,227.5 r90 top
C96 "S2P_CC-5.7x5x2.3-PX5.7+13" S2P_CC-5.7x5x2.3-PX5.7+13 308.5,219.5 r90 top
C97 "_UCZ1A221MCL1GS_" _UCZ1A221MCL1GS_ 85,205 r180 top
C98 "_UCZ1A221MCL1GS_+8" _UCZ1A221MCL1GS_+8 172.25,213 r90 top
C99 "_CGA6M3X7R1H225K200AB_+16" _CGA6M3X7R1H225K200AB_+16 179,212.75 r90 top
C100 "S2P_CC-1.6x0.8x0.8-PX1.6+49" S2P_CC-1.6x0.8x0.8-PX1.6+49 183,219.75 r180 top
C101 "S2P_CC-1.6x0.8x0.8-PX1.6+48" S2P_CC-1.6x0.8x0.8-PX1.6+48 122.25,221.25 r90 bottom
C110 "S2P_CC-1.6x0.8x0.8-PX1.6+53" S2P_CC-1.6x0.8x0.8-PX1.6+53 183,159.75 r180 top
C111 "S2P_CC-1.6x0.8x0.8-PX1.6+52" S2P_CC-1.6x0.8x0.8-PX1.6+52 122.25,161.25 r90 bottom
C113 "_CGA5L2X7R2A104K160AA_+1" _CGA5L2X7R2A104K160AA_+1 55.75,176.75 r0 top
C114 "S2P_CC-2x1.25x1.25-PX2+1" S2P_CC-2x1.25x1.25-PX2+1 68.5,179.75 r0 top
C115 "S2P_CC-1.6x0.8x0.8-PX1.6+74" S2P_CC-1.6x0.8x0.8-PX1.6+74 68.5,174.5 r180 top
C116 "_UCZ1K151MNS1MS_+2" _UCZ1K151MNS1MS_+2 80,172.5 r180 top
C117 "_UCZ1K151MNS1MS_+3" _UCZ1K151MNS1MS_+3 80,157.5 r180 top
C118 "S2P_CE-10.3x10.3x12.6-PX11+11" S2P_CE-10.3x10.3x12.6-PX11+11 99.5,186 r270 top
C119 "S2P_CE-10.3x10.3x12.6-PX11+12" S2P_CE-10.3x10.3x12.6-PX11+12 111,186 r270 top
C120 "S2P_CE-10.3x10.3x12.6-PX11+13" S2P_CE-10.3x10.3x12.6-PX11+13 122.5,186 r270 top
C121 "S2P_CE-10.3x10.3x12.6-PX11+14" S2P_CE-10.3x10.3x12.6-PX11+14 134,186 r270 top
C122 "S2P_CE-10.3x10.3x12.6-PX11+15" S2P_CE-10.3x10.3x12.6-PX11+15 145.5,186 r270 top
C123 "S2P_CE-10.3x10.3x12.6-PX11+16" S2P_CE-10.3x10.3x12.6-PX11+16 157,186 r270 top
C124 "S2P_CE-10.3x10.3x12.6-PX11+17" S2P_CE-10.3x10.3x12.6-PX11+17 151.25,170 r90 top
C125 "S2P_CE-10.3x10.3x12.6-PX11+18" S2P_CE-10.3x10.3x12.6-PX11+18 139.75,170 r90 top
C126 "S2P_CE-10.3x10.3x12.6-PX11+19" S2P_CE-10.3x10.3x12.6-PX11+19 128.25,170 r90 top
C127 "S2P_CE-10.3x10.3x12.6-PX11+20" S2P_CE-10.3x10.3x12.6-PX11+20 116.75,170 r90 top
C128 "S2P_CE-10.3x10.3x12.6-PX11+21" S2P_CE-10.3x10.3x12.6-PX11+21 105.25,170 r90 top
C129 "S2P_CC-5.7x5x2.3-PX5.7+22" S2P_CC-5.7x5x2.3-PX5.7+22 167.25,179 r180 top
C130 "S2P_CC-5.7x5x2.3-PX5.7+23" S2P_CC-5.7x5x2.3-PX5.7+23 167.25,172.75 r180 top
C131 "S2P_CC-5.7x5x2.3-PX5.7+24" S2P_CC-5.7x5x2.3-PX5.7+24 167.25,166.5 r180 top
C132 "S2P_CC-5.7x5x2.3-PX5.7+25" S2P_CC-5.7x5x2.3-PX5.7+25 167,179 r0 bottom
C133 "S2P_CC-5.7x5x2.3-PX5.7+26" S2P_CC-5.7x5x2.3-PX5.7+26 167,172.75 r0 bottom
C134 "S2P_CC-5.7x5x2.3-PX5.7+70" S2P_CC-5.7x5x2.3-PX5.7+70 167,166.5 r0 bottom
C135 "S2P_CC-5.7x5x2.3-PX5.7+27" S2P_CC-5.7x5x2.3-PX5.7+27 198,157 r0 top
C136 "S2P_CC-5.7x5x2.3-PX5.7+28" S2P_CC-5.7x5x2.3-PX5.7+28 198,163.25 r0 top
C137 "_CGA6M3X7R1H225K200AB_+2" _CGA6M3X7R1H225K200AB_+2 198.75,168.25 r180 top
C138 "S2P_CC-1.6x0.8x0.8-PX1.6+8" S2P_CC-1.6x0.8x0.8-PX1.6+8 199.5,171.5 r180 top
C139 "S2P_CC-1.6x0.8x0.8-PX1.6+55" S2P_CC-1.6x0.8x0.8-PX1.6+55 191.25,158.25 r0 top
C140 "S2P_CC-1.6x0.8x0.8-PX1.6+54" S2P_CC-1.6x0.8x0.8-PX1.6+54 187,159.75 r0 top
C141 "_CGA6M3X7R1H225K200AB_+3" _CGA6M3X7R1H225K200AB_+3 198.75,196.25 r0 top
C142 "S2P_CC-1.6x0.8x0.8-PX1.6+9" S2P_CC-1.6x0.8x0.8-PX1.6+9 167.25,191 r90 bottom
C143 "S2P_CC-1.6x0.8x0.8-PX1.6+10" S2P_CC-1.6x0.8x0.8-PX1.6+10 165.25,191 r90 bottom
C149 "S2P_CC-1.6x0.8x0.8-PX1.6+11" S2P_CC-1.6x0.8x0.8-PX1.6+11 223,154.75 r90 bottom
C150 "S2P_CC-1.6x0.8x0.8-PX1.6+12" S2P_CC-1.6x0.8x0.8-PX1.6+12 225,154.75 r90 bottom
C151 "_PCV1J390MCL2GS_+6" _PCV1J390MCL2GS_+6 236.5,190.5 r270 top
C152 "_PCV1J390MCL2GS_+7" _PCV1J390MCL2GS_+7 248,190.5 r270 top
C153 "_PCV1J390MCL2GS_+21" _PCV1J390MCL2GS_+21 236.5,173 r90 top
C154 "_PCV1J390MCL2GS_+20" _PCV1J390MCL2GS_+20 248,173 r90 top
C155 "_PCV1J390MCL2GS_+8" _PCV1J390MCL2GS_+8 249.5,157.5 r270 top
C156 "_PCV1J390MCL2GS_+9" _PCV1J390MCL2GS_+9 261,157.5 r270 top
C157 "_UCZ1J151MNQ1MS_+4" _UCZ1J151MNQ1MS_+4 261,190.5 r270 top
C158 "_UCZ1J151MNQ1MS_+5" _UCZ1J151MNQ1MS_+5 261,173 r90 top
C159 "S2P_CC-5.7x5x2.3-PX5.7+29" S2P_CC-5.7x5x2.3-PX5.7+29 228,173 r90 bottom
C160 "S2P_CC-5.7x5x2.3-PX5.7+30" S2P_CC-5.7x5x2.3-PX5.7+30 234.5,173 r90 bottom
C161 "S2P_CC-5.7x5x2.3-PX5.7+31" S2P_CC-5.7x5x2.3-PX5.7+31 241,173 r90 bottom
C162 "S2P_CC-5.7x5x2.3-PX5.7+32" S2P_CC-5.7x5x2.3-PX5.7+32 228,190.5 r270 bottom
C163 "S2P_CC-5.7x5x2.3-PX5.7+33" S2P_CC-5.7x5x2.3-PX5.7+33 234.5,190.5 r270 bottom
C164 "S2P_CC-5.7x5x2.3-PX5.7+34" S2P_CC-5.7x5x2.3-PX5.7+34 241,190.5 r270 bottom
C170 "_UCZ1A221MCL1GS_+9" _UCZ1A221MCL1GS_+9 294.5,146.75 r90 top
C171 "_UCZ1C221MCL1GS_+1" _UCZ1C221MCL1GS_+1 259,145.5 r0 top
C172 "_CGA6M3X7R1H225K200AB_+22" _CGA6M3X7R1H225K200AB_+22 152,153 r90 top
C173 "S2P_CC-1.6x0.8x0.8-PX1.6+70" S2P_CC-1.6x0.8x0.8-PX1.6+70 149.25,153 r90 top
C174 "_CGA6M3X7R1H225K200AB_+21" _CGA6M3X7R1H225K200AB_+21 158.5,153 r90 top
C175 "S2P_CC-1.6x0.8x0.8-PX1.6+71" S2P_CC-1.6x0.8x0.8-PX1.6+71 155.75,153 r90 top
C176 "S2P_CC-1.6x0.8x0.8-PX1.6+38" S2P_CC-1.6x0.8x0.8-PX1.6+38 122.25,157.5 r270 bottom
C177 "S2P_CC-1.6x0.8x0.8-PX1.6+13" S2P_CC-1.6x0.8x0.8-PX1.6+13 118,154 r0 bottom
C178 "_CGA6M3X7R1H225K200AB_+8" _CGA6M3X7R1H225K200AB_+8 110.5,144.25 r0 bottom
C179 "S2P_CC-1.6x0.8x0.8-PX1.6+45" S2P_CC-1.6x0.8x0.8-PX1.6+45 107.75,161.25 r90 bottom
C180 "S2P_CC-1.6x0.8x0.8-PX1.6+39" S2P_CC-1.6x0.8x0.8-PX1.6+39 113.75,157.5 r90 bottom
C181 "S2P_CC-5.7x5x2.3-PX5.7+35" S2P_CC-5.7x5x2.3-PX5.7+35 281,168.5 r270 bottom
C182 "S2P_CC-1.6x0.8x0.8-PX1.6+14" S2P_CC-1.6x0.8x0.8-PX1.6+14 276.5,170.75 r270 bottom
C183 "S2P_CC-1.6x0.8x0.8-PX1.6+65" S2P_CC-1.6x0.8x0.8-PX1.6+65 267.75,168 r90 bottom
C184 "S2P_CC-1.6x0.8x0.8-PX1.6+15" S2P_CC-1.6x0.8x0.8-PX1.6+15 273.75,174.25 r270 bottom
C197 "_UCZ1A221MCL1GS_+1" _UCZ1A221MCL1GS_+1 85,145 r180 top
C198 "_UCZ1A221MCL1GS_+2" _UCZ1A221MCL1GS_+2 172.25,153 r90 top
C199 "_CGA6M3X7R1H225K200AB_+9" _CGA6M3X7R1H225K200AB_+9 179,152.75 r90 top
C210 "S2P_CC-1.6x0.8x0.8-PX1.6+57" S2P_CC-1.6x0.8x0.8-PX1.6+57 183,99.75 r180 top
C211 "S2P_CC-1.6x0.8x0.8-PX1.6+56" S2P_CC-1.6x0.8x0.8-PX1.6+56 122.25,101.25 r90 bottom
C213 "_CGA5L2X7R2A104K160AA_+2" _CGA5L2X7R2A104K160AA_+2 55.75,116.75 r0 top
C214 "S2P_CC-2x1.25x1.25-PX2+2" S2P_CC-2x1.25x1.25-PX2+2 68.5,119.75 r0 top
C215 "S2P_CC-1.6x0.8x0.8-PX1.6+75" S2P_CC-1.6x0.8x0.8-PX1.6+75 68.5,114.5 r180 top
C216 "_UCZ1K151MNS1MS_+4" _UCZ1K151MNS1MS_+4 80,112.5 r180 top
C217 "_UCZ1K151MNS1MS_+5" _UCZ1K151MNS1MS_+5 80,97.5 r180 top
C218 "S2P_CE-10.3x10.3x12.6-PX11+22" S2P_CE-10.3x10.3x12.6-PX11+22 99.5,126 r270 top
C219 "S2P_CE-10.3x10.3x12.6-PX11+23" S2P_CE-10.3x10.3x12.6-PX11+23 111,126 r270 top
C220 "S2P_CE-10.3x10.3x12.6-PX11+24" S2P_CE-10.3x10.3x12.6-PX11+24 122.5,126 r270 top
C221 "S2P_CE-10.3x10.3x12.6-PX11+25" S2P_CE-10.3x10.3x12.6-PX11+25 134,126 r270 top
C222 "S2P_CE-10.3x10.3x12.6-PX11+26" S2P_CE-10.3x10.3x12.6-PX11+26 145.5,126 r270 top
C223 "S2P_CE-10.3x10.3x12.6-PX11+27" S2P_CE-10.3x10.3x12.6-PX11+27 157,126 r270 top
C224 "S2P_CE-10.3x10.3x12.6-PX11+28" S2P_CE-10.3x10.3x12.6-PX11+28 151.25,110 r90 top
C225 "S2P_CE-10.3x10.3x12.6-PX11+29" S2P_CE-10.3x10.3x12.6-PX11+29 139.75,110 r90 top
C226 "S2P_CE-10.3x10.3x12.6-PX11+30" S2P_CE-10.3x10.3x12.6-PX11+30 128.25,110 r90 top
C227 "S2P_CE-10.3x10.3x12.6-PX11+31" S2P_CE-10.3x10.3x12.6-PX11+31 116.75,110 r90 top
C228 "S2P_CE-10.3x10.3x12.6-PX11+32" S2P_CE-10.3x10.3x12.6-PX11+32 105.25,110 r90 top
C229 "S2P_CC-5.7x5x2.3-PX5.7+71" S2P_CC-5.7x5x2.3-PX5.7+71 167.25,119 r180 top
C230 "S2P_CC-5.7x5x2.3-PX5.7+36" S2P_CC-5.7x5x2.3-PX5.7+36 167.25,112.75 r180 top
C231 "S2P_CC-5.7x5x2.3-PX5.7+72" S2P_CC-5.7x5x2.3-PX5.7+72 167.25,106.5 r180 top
C232 "S2P_CC-5.7x5x2.3-PX5.7+37" S2P_CC-5.7x5x2.3-PX5.7+37 167,119 r0 bottom
C233 "S2P_CC-5.7x5x2.3-PX5.7+38" S2P_CC-5.7x5x2.3-PX5.7+38 167,112.75 r0 bottom
C234 "S2P_CC-5.7x5x2.3-PX5.7+39" S2P_CC-5.7x5x2.3-PX5.7+39 167,106.5 r0 bottom
C235 "S2P_CC-5.7x5x2.3-PX5.7+40" S2P_CC-5.7x5x2.3-PX5.7+40 198,97 r0 top
C236 "S2P_CC-5.7x5x2.3-PX5.7+41" S2P_CC-5.7x5x2.3-PX5.7+41 198,103.25 r0 top
C237 "_CGA6M3X7R1H225K200AB_+4" _CGA6M3X7R1H225K200AB_+4 198.75,108.25 r180 top
C238 "S2P_CC-1.6x0.8x0.8-PX1.6+16" S2P_CC-1.6x0.8x0.8-PX1.6+16 199.5,111.5 r180 top
C239 "S2P_CC-1.6x0.8x0.8-PX1.6+59" S2P_CC-1.6x0.8x0.8-PX1.6+59 191.25,98.25 r0 top
C240 "S2P_CC-1.6x0.8x0.8-PX1.6+58" S2P_CC-1.6x0.8x0.8-PX1.6+58 187,99.75 r0 top
C241 "_CGA6M3X7R1H225K200AB_+5" _CGA6M3X7R1H225K200AB_+5 198.75,136.25 r0 top
C242 "S2P_CC-1.6x0.8x0.8-PX1.6+17" S2P_CC-1.6x0.8x0.8-PX1.6+17 167.25,131 r90 bottom
C243 "S2P_CC-1.6x0.8x0.8-PX1.6+18" S2P_CC-1.6x0.8x0.8-PX1.6+18 165.25,131 r90 bottom
C249 "S2P_CC-1.6x0.8x0.8-PX1.6+19" S2P_CC-1.6x0.8x0.8-PX1.6+19 223,94.75 r90 bottom
C250 "S2P_CC-1.6x0.8x0.8-PX1.6+20" S2P_CC-1.6x0.8x0.8-PX1.6+20 225,94.75 r90 bottom
C251 "_PCV1J390MCL2GS_+10" _PCV1J390MCL2GS_+10 236.5,130.5 r270 top
C252 "_PCV1J390MCL2GS_+11" _PCV1J390MCL2GS_+11 248,130.5 r270 top
C253 "_PCV1J390MCL2GS_+22" _PCV1J390MCL2GS_+22 236.5,113 r90 top
C254 "_PCV1J390MCL2GS_+23" _PCV1J390MCL2GS_+23 248,113 r90 top
C255 "_PCV1J390MCL2GS_+12" _PCV1J390MCL2GS_+12 261,97.5 r270 top
C256 "_PCV1J390MCL2GS_+13" _PCV1J390MCL2GS_+13 249.5,97.5 r270 top
C257 "_UCZ1J151MNQ1MS_+7" _UCZ1J151MNQ1MS_+7 261,130.5 r270 top
C258 "_UCZ1J151MNQ1MS_+6" _UCZ1J151MNQ1MS_+6 261,113 r90 top
C259 "S2P_CC-5.7x5x2.3-PX5.7+42" S2P_CC-5.7x5x2.3-PX5.7+42 228,113 r90 bottom
C260 "S2P_CC-5.7x5x2.3-PX5.7+43" S2P_CC-5.7x5x2.3-PX5.7+43 234.5,113 r90 bottom
C261 "S2P_CC-5.7x5x2.3-PX5.7+44" S2P_CC-5.7x5x2.3-PX5.7+44 241,113 r90 bottom
C262 "S2P_CC-5.7x5x2.3-PX5.7+45" S2P_CC-5.7x5x2.3-PX5.7+45 228,130.5 r270 bottom
C263 "S2P_CC-5.7x5x2.3-PX5.7+46" S2P_CC-5.7x5x2.3-PX5.7+46 234.5,130.5 r270 bottom
C264 "S2P_CC-5.7x5x2.3-PX5.7+47" S2P_CC-5.7x5x2.3-PX5.7+47 241,130.5 r270 bottom
C270 "_UCZ1A221MCL1GS_+10" _UCZ1A221MCL1GS_+10 294.5,86.75 r90 top
C271 "_UCZ1C221MCL1GS_+2" _UCZ1C221MCL1GS_+2 259,85.5 r0 top
C272 "_CGA6M3X7R1H225K200AB_+17" _CGA6M3X7R1H225K200AB_+17 152,93 r90 top
C273 "S2P_CC-1.6x0.8x0.8-PX1.6+21" S2P_CC-1.6x0.8x0.8-PX1.6+21 149.25,93 r90 top
C274 "_CGA6M3X7R1H225K200AB_+18" _CGA6M3X7R1H225K200AB_+18 158.5,93 r90 top
C275 "S2P_CC-1.6x0.8x0.8-PX1.6+22" S2P_CC-1.6x0.8x0.8-PX1.6+22 155.75,93 r90 top
C276 "S2P_CC-1.6x0.8x0.8-PX1.6+40" S2P_CC-1.6x0.8x0.8-PX1.6+40 122.25,97.5 r270 bottom
C277 "S2P_CC-1.6x0.8x0.8-PX1.6+23" S2P_CC-1.6x0.8x0.8-PX1.6+23 118,94 r0 bottom
C278 "_CGA6M3X7R1H225K200AB_+10" _CGA6M3X7R1H225K200AB_+10 110.5,84.25 r0 bottom
C279 "S2P_CC-1.6x0.8x0.8-PX1.6+46" S2P_CC-1.6x0.8x0.8-PX1.6+46 107.75,101.25 r90 bottom
C280 "S2P_CC-1.6x0.8x0.8-PX1.6+41" S2P_CC-1.6x0.8x0.8-PX1.6+41 113.75,97.5 r90 bottom
C281 "S2P_CC-5.7x5x2.3-PX5.7+48" S2P_CC-5.7x5x2.3-PX5.7+48 281,108.5 r270 bottom
C282 "S2P_CC-1.6x0.8x0.8-PX1.6+24" S2P_CC-1.6x0.8x0.8-PX1.6+24 276.5,110.75 r270 bottom
C283 "S2P_CC-1.6x0.8x0.8-PX1.6+66" S2P_CC-1.6x0.8x0.8-PX1.6+66 267.75,108 r90 bottom
C284 "S2P_CC-1.6x0.8x0.8-PX1.6+25" S2P_CC-1.6x0.8x0.8-PX1.6+25 273.75,114.25 r270 bottom
C297 "_UCZ1A221MCL1GS_+3" _UCZ1A221MCL1GS_+3 85,85 r180 top
C298 "_UCZ1A221MCL1GS_+4" _UCZ1A221MCL1GS_+4 172.25,93 r90 top
C299 "_CGA6M3X7R1H225K200AB_+11" _CGA6M3X7R1H225K200AB_+11 179,92.75 r90 top
C310 "S2P_CC-1.6x0.8x0.8-PX1.6+61" S2P_CC-1.6x0.8x0.8-PX1.6+61 183,39.75 r180 top
C311 "S2P_CC-1.6x0.8x0.8-PX1.6+60" S2P_CC-1.6x0.8x0.8-PX1.6+60 122.25,41.25 r90 bottom
C313 "_CGA5L2X7R2A104K160AA_+3" _CGA5L2X7R2A104K160AA_+3 55.75,56.75 r0 top
C314 "S2P_CC-2x1.25x1.25-PX2+3" S2P_CC-2x1.25x1.25-PX2+3 68.5,59.75 r0 top
C315 "S2P_CC-1.6x0.8x0.8-PX1.6+72" S2P_CC-1.6x0.8x0.8-PX1.6+72 68.5,54.5 r180 top
C316 "_UCZ1K151MNS1MS_+6" _UCZ1K151MNS1MS_+6 80,52.5 r180 top
C317 "_UCZ1K151MNS1MS_+7" _UCZ1K151MNS1MS_+7 80,37.5 r180 top
C318 "S2P_CE-10.3x10.3x12.6-PX11+33" S2P_CE-10.3x10.3x12.6-PX11+33 99.5,66 r270 top
C319 "S2P_CE-10.3x10.3x12.6-PX11+34" S2P_CE-10.3x10.3x12.6-PX11+34 111,66 r270 top
C320 "S2P_CE-10.3x10.3x12.6-PX11+35" S2P_CE-10.3x10.3x12.6-PX11+35 122.5,66 r270 top
C321 "S2P_CE-10.3x10.3x12.6-PX11+36" S2P_CE-10.3x10.3x12.6-PX11+36 134,66 r270 top
C322 "S2P_CE-10.3x10.3x12.6-PX11+37" S2P_CE-10.3x10.3x12.6-PX11+37 145.5,66 r270 top
C323 "S2P_CE-10.3x10.3x12.6-PX11+38" S2P_CE-10.3x10.3x12.6-PX11+38 157,66 r270 top
C324 "S2P_CE-10.3x10.3x12.6-PX11+39" S2P_CE-10.3x10.3x12.6-PX11+39 151.25,50 r90 top
C325 "S2P_CE-10.3x10.3x12.6-PX11+40" S2P_CE-10.3x10.3x12.6-PX11+40 139.75,50 r90 top
C326 "S2P_CE-10.3x10.3x12.6-PX11+41" S2P_CE-10.3x10.3x12.6-PX11+41 128.25,50 r90 top
C327 "S2P_CE-10.3x10.3x12.6-PX11+42" S2P_CE-10.3x10.3x12.6-PX11+42 116.75,50 r90 top
C328 "S2P_CE-10.3x10.3x12.6-PX11+43" S2P_CE-10.3x10.3x12.6-PX11+43 105.25,50 r90 top
C329 "S2P_CC-5.7x5x2.3-PX5.7+73" S2P_CC-5.7x5x2.3-PX5.7+73 167.25,59 r180 top
C330 "S2P_CC-5.7x5x2.3-PX5.7+74" S2P_CC-5.7x5x2.3-PX5.7+74 167.25,52.75 r180 top
C331 "S2P_CC-5.7x5x2.3-PX5.7+75" S2P_CC-5.7x5x2.3-PX5.7+75 167.25,46.5 r180 top
C332 "S2P_CC-5.7x5x2.3-PX5.7+49" S2P_CC-5.7x5x2.3-PX5.7+49 167,59 r0 bottom
C333 "S2P_CC-5.7x5x2.3-PX5.7+50" S2P_CC-5.7x5x2.3-PX5.7+50 167,52.75 r0 bottom
C334 "S2P_CC-5.7x5x2.3-PX5.7+51" S2P_CC-5.7x5x2.3-PX5.7+51 167,46.5 r0 bottom
C335 "S2P_CC-5.7x5x2.3-PX5.7+52" S2P_CC-5.7x5x2.3-PX5.7+52 198,37 r0 top
C336 "S2P_CC-5.7x5x2.3-PX5.7+53" S2P_CC-5.7x5x2.3-PX5.7+53 198,43.25 r0 top
C337 "_CGA6M3X7R1H225K200AB_+6" _CGA6M3X7R1H225K200AB_+6 198.75,48.25 r180 top
C338 "S2P_CC-1.6x0.8x0.8-PX1.6+26" S2P_CC-1.6x0.8x0.8-PX1.6+26 199.5,51.5 r180 top
C339 "S2P_CC-1.6x0.8x0.8-PX1.6+63" S2P_CC-1.6x0.8x0.8-PX1.6+63 191.25,38.25 r0 top
C340 "S2P_CC-1.6x0.8x0.8-PX1.6+62" S2P_CC-1.6x0.8x0.8-PX1.6+62 187,39.75 r0 top
C341 "_CGA6M3X7R1H225K200AB_+7" _CGA6M3X7R1H225K200AB_+7 198.75,76.25 r0 top
C342 "S2P_CC-1.6x0.8x0.8-PX1.6+27" S2P_CC-1.6x0.8x0.8-PX1.6+27 167.25,71 r90 bottom
C343 "S2P_CC-1.6x0.8x0.8-PX1.6+28" S2P_CC-1.6x0.8x0.8-PX1.6+28 165.25,71 r90 bottom
C349 "S2P_CC-1.6x0.8x0.8-PX1.6+29" S2P_CC-1.6x0.8x0.8-PX1.6+29 223,34.75 r90 bottom
C350 "S2P_CC-1.6x0.8x0.8-PX1.6+30" S2P_CC-1.6x0.8x0.8-PX1.6+30 225,34.75 r90 bottom
C351 "_PCV1J390MCL2GS_+14" _PCV1J390MCL2GS_+14 236.5,70.5 r270 top
C352 "_PCV1J390MCL2GS_+15" _PCV1J390MCL2GS_+15 248,70.5 r270 top
C353 "_PCV1J390MCL2GS_+16" _PCV1J390MCL2GS_+16 236.5,53 r90 top
C354 "_PCV1J390MCL2GS_+17" _PCV1J390MCL2GS_+17 248,53 r90 top
C355 "_PCV1J390MCL2GS_+18" _PCV1J390MCL2GS_+18 249.5,37.5 r270 top
C356 "_PCV1J390MCL2GS_+19" _PCV1J390MCL2GS_+19 261,37.5 r270 top
C357 "_UCZ1J151MNQ1MS_+2" _UCZ1J151MNQ1MS_+2 261,70.5 r270 top
C358 "_UCZ1J151MNQ1MS_+3" _UCZ1J151MNQ1MS_+3 261,53 r90 top
C359 "S2P_CC-5.7x5x2.3-PX5.7+54" S2P_CC-5.7x5x2.3-PX5.7+54 228,53 r90 bottom
C360 "S2P_CC-5.7x5x2.3-PX5.7+55" S2P_CC-5.7x5x2.3-PX5.7+55 234.5,53 r90 bottom
C361 "S2P_CC-5.7x5x2.3-PX5.7+56" S2P_CC-5.7x5x2.3-PX5.7+56 241,53 r90 bottom
C362 "S2P_CC-5.7x5x2.3-PX5.7+57" S2P_CC-5.7x5x2.3-PX5.7+57 228,70.5 r270 bottom
C363 "S2P_CC-5.7x5x2.3-PX5.7+58" S2P_CC-5.7x5x2.3-PX5.7+58 234.5,70.5 r270 bottom
C364 "S2P_CC-5.7x5x2.3-PX5.7+59" S2P_CC-5.7x5x2.3-PX5.7+59 241,70.5 r270 bottom
C370 "_UCZ1A221MCL1GS_+11" _UCZ1A221MCL1GS_+11 294.5,26.75 r90 top
C371 "_UCZ1C221MCL1GS_+3" _UCZ1C221MCL1GS_+3 259,25.5 r0 top
C372 "_CGA6M3X7R1H225K200AB_+19" _CGA6M3X7R1H225K200AB_+19 152,33 r90 top
C373 "S2P_CC-1.6x0.8x0.8-PX1.6+31" S2P_CC-1.6x0.8x0.8-PX1.6+31 149.25,33 r90 top
C374 "_CGA6M3X7R1H225K200AB_+20" _CGA6M3X7R1H225K200AB_+20 158.5,33 r90 top
C375 "S2P_CC-1.6x0.8x0.8-PX1.6+32" S2P_CC-1.6x0.8x0.8-PX1.6+32 155.75,33 r90 top
C376 "S2P_CC-1.6x0.8x0.8-PX1.6+42" S2P_CC-1.6x0.8x0.8-PX1.6+42 122.25,37.5 r270 bottom
C377 "S2P_CC-1.6x0.8x0.8-PX1.6+33" S2P_CC-1.6x0.8x0.8-PX1.6+33 118,34 r0 bottom
C378 "_CGA6M3X7R1H225K200AB_+12" _CGA6M3X7R1H225K200AB_+12 110.5,24.25 r0 bottom
C379 "S2P_CC-1.6x0.8x0.8-PX1.6+47" S2P_CC-1.6x0.8x0.8-PX1.6+47 107.75,41.25 r90 bottom
C380 "S2P_CC-1.6x0.8x0.8-PX1.6+43" S2P_CC-1.6x0.8x0.8-PX1.6+43 113.75,37.5 r90 bottom
C381 "S2P_CC-5.7x5x2.3-PX5.7+60" S2P_CC-5.7x5x2.3-PX5.7+60 281,48.5 r270 bottom
C382 "S2P_CC-1.6x0.8x0.8-PX1.6+34" S2P_CC-1.6x0.8x0.8-PX1.6+34 276.5,50.75 r270 bottom
C383 "S2P_CC-1.6x0.8x0.8-PX1.6+67" S2P_CC-1.6x0.8x0.8-PX1.6+67 267.75,48 r90 bottom
C384 "S2P_CC-1.6x0.8x0.8-PX1.6+35" S2P_CC-1.6x0.8x0.8-PX1.6+35 273.75,54.25 r270 bottom
C397 "_UCZ1A221MCL1GS_+5" _UCZ1A221MCL1GS_+5 85,25 r180 top
C398 "_UCZ1A221MCL1GS_+6" _UCZ1A221MCL1GS_+6 172.25,33 r90 top
C399 "_CGA6M3X7R1H225K200AB_+13" _CGA6M3X7R1H225K200AB_+13 179,32.75 r90 top
C401 "_CGA5F2C0G1H333J085AD_+7" _CGA5F2C0G1H333J085AD_+7 166,256 r0 top
C403 "_CGA5F2C0G1H333J085AD_" _CGA5F2C0G1H333J085AD_ 224,216.75 r0 top
C405 "_CGA5L2C0G1H104J160AA_" _CGA5L2C0G1H104J160AA_ 215.5,216.75 r0 top
C411 "_CGA5F2C0G1H333J085AD_+1" _CGA5F2C0G1H333J085AD_+1 166,196 r0 top
C413 "_CGA5F2C0G1H333J085AD_+2" _CGA5F2C0G1H333J085AD_+2 224,156.75 r0 top
C415 "_CGA5L2C0G1H104J160AA_+3" _CGA5L2C0G1H104J160AA_+3 215.5,156.75 r0 top
C421 "_CGA5F2C0G1H333J085AD_+3" _CGA5F2C0G1H333J085AD_+3 166,136 r0 top
C423 "_CGA5F2C0G1H333J085AD_+4" _CGA5F2C0G1H333J085AD_+4 224,96.75 r0 top
C425 "_CGA5L2C0G1H104J160AA_+2" _CGA5L2C0G1H104J160AA_+2 215.5,96.75 r0 top
C431 "_CGA5F2C0G1H333J085AD_+5" _CGA5F2C0G1H333J085AD_+5 166,76 r0 top
C433 "_CGA5F2C0G1H333J085AD_+6" _CGA5F2C0G1H333J085AD_+6 224,36.75 r0 top
C435 "_CGA5L2C0G1H104J160AA_+1" _CGA5L2C0G1H104J160AA_+1 215.5,36.75 r0 top
C436 "_CGA5L2X7R2A104K160AA_" _CGA5L2X7R2A104K160AA_ 197.419,243.426 r180 top
C437 "_CGA5L2X7R2A104K160AA_" _CGA5L2X7R2A104K160AA_ 197.419,183.355 r180 top
C438 "_CGA5L2X7R2A104K160AA_" _CGA5L2X7R2A104K160AA_ 197.419,123.347 r180 top
C439 "_CGA5L2X7R2A104K160AA_" _CGA5L2X7R2A104K160AA_ 197.419,63.34 r180 top
C440 "S2P_CC-1.6x0.8x0.8-PX1.6" S2P_CC-1.6x0.8x0.8-PX1.6#2 269.555,241.775 r0 bottom
C441 "S2P_CC-1.6x0.8x0.8-PX1.6" S2P_CC-1.6x0.8x0.8-PX1.6#2 269.555,181.775 r0 bottom
C442 "S2P_CC-1.6x0.8x0.8-PX1.6" S2P_CC-1.6x0.8x0.8-PX1.6#2 269.555,121.775 r0 bottom
C443 "S2P_CC-1.6x0.8x0.8-PX1.6" S2P_CC-1.6x0.8x0.8-PX1.6#2 269.555,61.775 r0 bottom
C444 "S2P_CC-1.6x0.8x0.8-PX1.6" S2P_CC-1.6x0.8x0.8-PX1.6#1 52.385,241.775 r270 top
C445 "S2P_CC-1.6x0.8x0.8-PX1.6" S2P_CC-1.6x0.8x0.8-PX1.6#1 52.385,181.767 r270 top
C446 "S2P_CC-1.6x0.8x0.8-PX1.6" S2P_CC-1.6x0.8x0.8-PX1.6#1 52.385,121.76 r270 top
C447 "S2P_CC-1.6x0.8x0.8-PX1.6" S2P_CC-1.6x0.8x0.8-PX1.6#1 52.385,61.752 r270 top
CN1 "D6P_CN-17.4x5.75x7-PX2.5-H1.1" D6P_CN-17.4x5.75x7-PX2.5-H1.1 168.5,204.5 r180 top
CN2 "D9P_CN-24.9x5.75x7-PX2.5-H1.1" D9P_CN-24.9x5.75x7-PX2.5-H1.1 145,203.5 r0 top
CN3 "D8P_CN-22.4x5.75x7-PX2.5-H1.1" D8P_CN-22.4x5.75x7-PX2.5-H1.1 277.25,203.5 r0 top
CN4 "D5P_CN-14.9x5.75x7-PX2.5-H1.1" D5P_CN-14.9x5.75x7-PX2.5-H1.1 99.5,204.25 r180 top
CN5 "_B2B-EH_" _B2B-EH_ 183,263 r180 top
CN6 "D2P_CN-7.4x5.75x7-PX2.5-H1.1" D2P_CN-7.4x5.75x7-PX2.5-H1.1 50,204 r0 top
CN7 "D3P_CN-9.9x5.75x7-PX2.5-H1.1" D3P_CN-9.9x5.75x7-PX2.5-H1.1 306.25,204 r0 top
CN8 "_B2P-VH_" _B2P-VH_ 167.25,247.5 r0 top
CN9 "_B2P-VH_" _B2P-VH_ 224,210 r180 top
CN10 "_B2P-VH_" _B2P-VH_ 214.5,210 r180 top
CN11 "_TSM-102-01-L-SV_" _TSM-102-01-L-SV_ 164,211.5 r90 top
CN12 "_TSM-102-01-L-SV_+1" _TSM-102-01-L-SV_+1 183.5,209.25 r90 top
CN13 "_TSM-102-01-L-SV_+2" _TSM-102-01-L-SV_+2 94,211 r180 top
CN14 "_TSM-102-01-L-SV_+3" _TSM-102-01-L-SV_+3 283.25,211.25 r0 top
CN15 "_TSM-102-01-L-SV_+4" _TSM-102-01-L-SV_+4 271,211 r180 top
CN16 "_TSW-101-07-G-S_" _TSW-101-07-G-S_ 127.5,217 r0 top
CN17 "_TSW-101-07-G-S_" _TSW-101-07-G-S_ 110.75,214.5 r0 top
CN18 "_TSM-102-01-L-SV_+5" _TSM-102-01-L-SV_+5 132.5,214.5 r180 top
CN19 "_TSM-102-01-L-SV_+6" _TSM-102-01-L-SV_+6 122,214.5 r0 top
CN20 "_TSW-101-07-G-S_" _TSW-101-07-G-S_ 268,223.875 r0 top
CN21 "_HW-1-S_" _HW-1-S_ 298.125,258.375 r180 top
CN22 "_HW-1-S_+1" _HW-1-S_+1 298,234 r0 top
CN23 "_TSW-101-07-G-S_" _TSW-101-07-G-S_ 279.875,222.45 r0 top
CN24 "_HW-1-S_+2" _HW-1-S_+2 277.25,214.5 r0 top
CN25 "_HW-1-S_+3" _HW-1-S_+3 288.25,211 r90 top
CN26 "_HW-1-S_+4" _HW-1-S_+4 74.5,205 r0 top
CN27 "_HW-1-S_+5" _HW-1-S_+5 167.75,220.5 r0 top
CN28 "_HW-1-S_+6" _HW-1-S_+6 177.75,219.25 r0 top
CN29 "_TSW-101-07-G-S_" _TSW-101-07-G-S_ 179.5,242.125 r0 top
CN30 "_TSW-101-07-G-S_" _TSW-101-07-G-S_ 183.5,254.5 r0 top
CN31 "_TSW-101-07-G-S_" _TSW-101-07-G-S_ 187.5,242.125 r0 top
CN32 "_TSW-101-07-G-S_" _TSW-101-07-G-S_ 181.595,233.25 r0 top
CN33 "_TSW-101-07-G-S_" _TSW-101-07-G-S_ 183.5,238.5 r0 top
CN34 "_TSW-101-07-G-S_" _TSW-101-07-G-S_ 185.25,233.25 r0 top
CN101 "D6P_CN-17.4x5.75x7-PX2.5-H1.1" D6P_CN-17.4x5.75x7-PX2.5-H1.1 168.5,144.5 r180 top
CN102 "D9P_CN-24.9x5.75x7-PX2.5-H1.1" D9P_CN-24.9x5.75x7-PX2.5-H1.1 145,143.5 r0 top
CN103 "D8P_CN-22.4x5.75x7-PX2.5-H1.1" D8P_CN-22.4x5.75x7-PX2.5-H1.1 277.25,143.5 r0 top
CN104 "D5P_CN-14.9x5.75x7-PX2.5-H1.1" D5P_CN-14.9x5.75x7-PX2.5-H1.1 99.5,144.25 r180 top
CN105 "_B2B-EH_" _B2B-EH_ 183,203 r180 top
CN108 "_B2P-VH_" _B2P-VH_ 167.25,187.5 r0 top
CN109 "_B2P-VH_" _B2P-VH_ 224,150 r180 top
CN110 "_B2P-VH_" _B2P-VH_ 214.5,150 r180 top
CN111 "_TSM-102-01-L-SV_+7" _TSM-102-01-L-SV_+7 164,151.5 r90 top
CN112 "_TSM-102-01-L-SV_+8" _TSM-102-01-L-SV_+8 183.5,149.25 r90 top
CN113 "_TSM-102-01-L-SV_+9" _TSM-102-01-L-SV_+9 94,151 r180 top
CN114 "_TSM-102-01-L-SV_+10" _TSM-102-01-L-SV_+10 283.25,151.25 r0 top
CN115 "_TSM-102-01-L-SV_+11" _TSM-102-01-L-SV_+11 271,151 r180 top
CN116 "_TSW-101-07-G-S_" _TSW-101-07-G-S_ 127.5,157 r0 top
CN117 "_TSW-101-07-G-S_" _TSW-101-07-G-S_ 110.75,154.5 r0 top
CN118 "_TSM-102-01-L-SV_+12" _TSM-102-01-L-SV_+12 132.5,154.5 r180 top
CN119 "_TSM-102-01-L-SV_+13" _TSM-102-01-L-SV_+13 122,154.5 r0 top
CN120 "_TSW-101-07-G-S_" _TSW-101-07-G-S_ 268,163.875 r0 top
CN121 "_HW-1-S_+7" _HW-1-S_+7 298.125,198.375 r0 top
CN122 "_HW-1-S_+8" _HW-1-S_+8 298,174 r0 top
CN123 "_TSW-101-07-G-S_" _TSW-101-07-G-S_ 279.875,162.45 r0 top
CN124 "_HW-1-S_+9" _HW-1-S_+9 277.25,154.5 r0 top
CN125 "_HW-1-S_+10" _HW-1-S_+10 288.25,151 r90 top
CN126 "_HW-1-S_+11" _HW-1-S_+11 74.5,145 r0 top
CN127 "_HW-1-S_+12" _HW-1-S_+12 167.75,160.5 r0 top
CN128 "_HW-1-S_+13" _HW-1-S_+13 177.75,159.25 r0 top
CN129 "_TSW-101-07-G-S_" _TSW-101-07-G-S_ 179.5,182.125 r0 top
CN130 "_TSW-101-07-G-S_" _TSW-101-07-G-S_ 183.5,194.5 r0 top
CN131 "_TSW-101-07-G-S_" _TSW-101-07-G-S_ 187.5,182.125 r0 top
CN132 "_TSW-101-07-G-S_" _TSW-101-07-G-S_ 181.595,173.25 r0 top
CN133 "_TSW-101-07-G-S_" _TSW-101-07-G-S_ 183.5,178.5 r0 top
CN134 "_TSW-101-07-G-S_" _TSW-101-07-G-S_ 185.25,173.25 r0 top
CN201 "D6P_CN-17.4x5.75x7-PX2.5-H1.1" D6P_CN-17.4x5.75x7-PX2.5-H1.1 168.5,84.5 r180 top
CN202 "D9P_CN-24.9x5.75x7-PX2.5-H1.1" D9P_CN-24.9x5.75x7-PX2.5-H1.1 145,83.5 r0 top
CN203 "D8P_CN-22.4x5.75x7-PX2.5-H1.1" D8P_CN-22.4x5.75x7-PX2.5-H1.1 277.25,83.5 r0 top
CN204 "D5P_CN-14.9x5.75x7-PX2.5-H1.1" D5P_CN-14.9x5.75x7-PX2.5-H1.1 99.5,84.25 r180 top
CN205 "_B2B-EH_" _B2B-EH_ 183,143 r180 top
CN208 "_B2P-VH_" _B2P-VH_ 167.25,127.5 r0 top
CN209 "_B2P-VH_" _B2P-VH_ 224,90 r180 top
CN210 "_B2P-VH_" _B2P-VH_ 214.5,90 r180 top
CN211 "_TSM-102-01-L-SV_+14" _TSM-102-01-L-SV_+14 164,91.5 r90 top
CN212 "_TSM-102-01-L-SV_+15" _TSM-102-01-L-SV_+15 183.5,89.25 r90 top
CN213 "_TSM-102-01-L-SV_+16" _TSM-102-01-L-SV_+16 94,91 r180 top
CN214 "_TSM-102-01-L-SV_+17" _TSM-102-01-L-SV_+17 283.25,91.25 r0 top
CN215 "_TSM-102-01-L-SV_+18" _TSM-102-01-L-SV_+18 271,91 r180 top
CN216 "_TSW-101-07-G-S_" _TSW-101-07-G-S_ 127.5,97 r0 top
CN217 "_TSW-101-07-G-S_" _TSW-101-07-G-S_ 110.75,94.5 r0 top
CN218 "_TSM-102-01-L-SV_+19" _TSM-102-01-L-SV_+19 132.5,94.5 r180 top
CN219 "_TSM-102-01-L-SV_+20" _TSM-102-01-L-SV_+20 122,94.5 r0 top
CN220 "_TSW-101-07-G-S_" _TSW-101-07-G-S_ 268,103.875 r0 top
CN221 "_HW-1-S_+14" _HW-1-S_+14 298.125,138.375 r0 top
CN222 "_HW-1-S_+15" _HW-1-S_+15 298,114 r0 top
CN223 "_TSW-101-07-G-S_" _TSW-101-07-G-S_ 279.875,102.45 r0 top
CN224 "_HW-1-S_+16" _HW-1-S_+16 277.25,94.5 r0 top
CN225 "_HW-1-S_+17" _HW-1-S_+17 288.25,91 r90 top
CN226 "_HW-1-S_+18" _HW-1-S_+18 74.5,85 r0 top
CN227 "_HW-1-S_+19" _HW-1-S_+19 167.75,100.5 r0 top
CN228 "_HW-1-S_+20" _HW-1-S_+20 177.75,99.25 r0 top
CN229 "_TSW-101-07-G-S_" _TSW-101-07-G-S_ 179.5,122.125 r0 top
CN230 "_TSW-101-07-G-S_" _TSW-101-07-G-S_ 183.5,134.5 r0 top
CN231 "_TSW-101-07-G-S_" _TSW-101-07-G-S_ 187.5,122.125 r0 top
CN232 "_TSW-101-07-G-S_" _TSW-101-07-G-S_ 181.595,113.25 r0 top
CN233 "_TSW-101-07-G-S_" _TSW-101-07-G-S_ 183.5,118.5 r0 top
CN234 "_TSW-101-07-G-S_" _TSW-101-07-G-S_ 185.25,113.25 r0 top
CN301 "D6P_CN-17.4x5.75x7-PX2.5-H1.1" D6P_CN-17.4x5.75x7-PX2.5-H1.1 168.5,24.5 r180 top
CN302 "D9P_CN-24.9x5.75x7-PX2.5-H1.1" D9P_CN-24.9x5.75x7-PX2.5-H1.1 145,23.5 r0 top
CN303 "D8P_CN-22.4x5.75x7-PX2.5-H1.1" D8P_CN-22.4x5.75x7-PX2.5-H1.1 277.25,23.5 r0 top
CN304 "D5P_CN-14.9x5.75x7-PX2.5-H1.1" D5P_CN-14.9x5.75x7-PX2.5-H1.1 99.5,24.25 r180 top
CN305 "_B2B-EH_" _B2B-EH_ 183,83 r180 top
CN308 "_B2P-VH_" _B2P-VH_ 167.25,67.5 r0 top
CN309 "_B2P-VH_" _B2P-VH_ 224,30 r180 top
CN310 "_B2P-VH_" _B2P-VH_ 214.5,30 r180 top
CN311 "_TSM-102-01-L-SV_+21" _TSM-102-01-L-SV_+21 164,31.5 r90 top
CN312 "_TSM-102-01-L-SV_+22" _TSM-102-01-L-SV_+22 183.5,29.25 r90 top
CN313 "_TSM-102-01-L-SV_+23" _TSM-102-01-L-SV_+23 94,31 r180 top
CN314 "_TSM-102-01-L-SV_+24" _TSM-102-01-L-SV_+24 283.25,31.25 r0 top
CN315 "_TSM-102-01-L-SV_+25" _TSM-102-01-L-SV_+25 271,31 r180 top
CN316 "_TSW-101-07-G-S_" _TSW-101-07-G-S_ 127.5,37 r0 top
CN317 "_TSW-101-07-G-S_" _TSW-101-07-G-S_ 110.75,34.5 r0 top
CN318 "_TSM-102-01-L-SV_+26" _TSM-102-01-L-SV_+26 132.5,34.5 r180 top
CN319 "_TSM-102-01-L-SV_+27" _TSM-102-01-L-SV_+27 122,34.5 r0 top
CN320 "_TSW-101-07-G-S_" _TSW-101-07-G-S_ 268,43.875 r0 top
CN321 "_HW-1-S_+21" _HW-1-S_+21 298.125,78.375 r0 top
CN322 "_HW-1-S_+22" _HW-1-S_+22 298,54 r0 top
CN323 "_TSW-101-07-G-S_" _TSW-101-07-G-S_ 279.875,42.45 r0 top
CN324 "_HW-1-S_+23" _HW-1-S_+23 277.25,34.5 r0 top
CN325 "_HW-1-S_+24" _HW-1-S_+24 288.25,31 r90 top
CN326 "_HW-1-S_+25" _HW-1-S_+25 74.5,25 r0 top
CN327 "_HW-1-S_+26" _HW-1-S_+26 167.75,40.5 r0 top
CN328 "_HW-1-S_+27" _HW-1-S_+27 177.75,39.25 r0 top
CN329 "_TSW-101-07-G-S_" _TSW-101-07-G-S_ 179.5,62.125 r0 top
CN330 "_TSW-101-07-G-S_" _TSW-101-07-G-S_ 183.5,74.5 r0 top
CN331 "_TSW-101-07-G-S_" _TSW-101-07-G-S_ 187.5,62.125 r0 top
CN332 "_TSW-101-07-G-S_" _TSW-101-07-G-S_ 181.595,53.25 r0 top
CN333 "_TSW-101-07-G-S_" _TSW-101-07-G-S_ 183.5,58.5 r0 top
CN334 "_TSW-101-07-G-S_" _TSW-101-07-G-S_ 185.25,53.25 r0 top
D1 "S2P_D-4.3x3.6x2.45-PX5.4" S2P_D-4.3x3.6x2.45-PX5.4 50,213 r180 top
D2 "S2P_D-3.8x2.4x1-PX4.7" S2P_D-3.8x2.4x1-PX4.7 175.25,250.5 r0 top
D3 "S2P_D-3.8x2.4x1-PX4.7+2" S2P_D-3.8x2.4x1-PX4.7+2 183,250.5 r0 top
D4 "S2P_D-3.8x2.4x1-PX4.7+4" S2P_D-3.8x2.4x1-PX4.7+4 190.75,250.5 r0 top
D5 "S2P_D-4.32x2.6x2.2-PX5.21" S2P_D-4.32x2.6x2.2-PX5.21 198.75,252.5 r180 top
D6 "S2P_D-3.8x2.4x1-PX4.7+1" S2P_D-3.8x2.4x1-PX4.7+1 174.5,222.5 r0 top
D7 "S2P_D-3.8x2.4x1-PX4.7+3" S2P_D-3.8x2.4x1-PX4.7+3 181.5,222.5 r0 top
D8 "S2P_D-3.8x2.4x1-PX4.7+5" S2P_D-3.8x2.4x1-PX4.7+5 188.5,222.5 r0 top
D11 "_1SS403_" _1SS403_ 276,221.25 r270 bottom
D12 "_1SS403_+1" _1SS403_+1 278.5,221.25 r270 bottom
D13 "_1SS403_+2" _1SS403_+2 281.25,221.25 r270 bottom
D15 "_SZ1SMA24AT3G_" _SZ1SMA24AT3G_ 315.5,235.75 r270 top
D16 "_SZ1SMA24AT3G_+1" _SZ1SMA24AT3G_+1 315.5,228.25 r90 top
D17 "_1SS403_+13" _1SS403_+13 266.5,234.5 r270 bottom
D18 "_1SS403_+14" _1SS403_+14 281,235.75 r180 bottom
D19 "S2P_ZD-0.8x1.2x0.6-PY1.6" S2P_ZD-0.8x1.2x0.6-PY1.6 275.75,238.75 r180 bottom
D20 "_1SS403_+15" _1SS403_+15 273.5,238.75 r90 bottom
D21 "S2P_ZD-0.8x1.2x0.6-PY1.6+1" S2P_ZD-0.8x1.2x0.6-PY1.6+1 276.75,235.75 r90 bottom
D102 "S2P_D-3.8x2.4x1-PX4.7+6" S2P_D-3.8x2.4x1-PX4.7+6 175.25,190.5 r0 top
D103 "S2P_D-3.8x2.4x1-PX4.7+7" S2P_D-3.8x2.4x1-PX4.7+7 183,190.5 r0 top
D104 "S2P_D-3.8x2.4x1-PX4.7+8" S2P_D-3.8x2.4x1-PX4.7+8 190.75,190.5 r0 top
D105 "S2P_D-4.32x2.6x2.2-PX5.21+1" S2P_D-4.32x2.6x2.2-PX5.21+1 198.75,192.5 r180 top
D106 "S2P_D-3.8x2.4x1-PX4.7+9" S2P_D-3.8x2.4x1-PX4.7+9 174.5,162.5 r0 top
D107 "S2P_D-3.8x2.4x1-PX4.7+10" S2P_D-3.8x2.4x1-PX4.7+10 181.5,162.5 r0 top
D108 "S2P_D-3.8x2.4x1-PX4.7+11" S2P_D-3.8x2.4x1-PX4.7+11 188.5,162.5 r0 top
D111 "_1SS403_+3" _1SS403_+3 276,161.25 r270 bottom
D112 "_1SS403_+4" _1SS403_+4 278.5,161.25 r270 bottom
D113 "_1SS403_+5" _1SS403_+5 281.25,161.25 r270 bottom
D117 "_1SS403_+16" _1SS403_+16 266.5,174.5 r270 bottom
D118 "_1SS403_+17" _1SS403_+17 281,175.75 r180 bottom
D119 "S2P_ZD-0.8x1.2x0.6-PY1.6+2" S2P_ZD-0.8x1.2x0.6-PY1.6+2 275.75,178.75 r180 bottom
D120 "_1SS403_+18" _1SS403_+18 273.75,178.75 r90 bottom
D121 "S2P_ZD-0.8x1.2x0.6-PY1.6+3" S2P_ZD-0.8x1.2x0.6-PY1.6+3 276.75,175.75 r90 bottom
D202 "S2P_D-3.8x2.4x1-PX4.7+12" S2P_D-3.8x2.4x1-PX4.7+12 175.25,130.5 r0 top
D203 "S2P_D-3.8x2.4x1-PX4.7+13" S2P_D-3.8x2.4x1-PX4.7+13 183,130.5 r0 top
D204 "S2P_D-3.8x2.4x1-PX4.7+14" S2P_D-3.8x2.4x1-PX4.7+14 190.75,130.5 r0 top
D205 "S2P_D-4.32x2.6x2.2-PX5.21+2" S2P_D-4.32x2.6x2.2-PX5.21+2 198.75,132.5 r180 top
D206 "S2P_D-3.8x2.4x1-PX4.7+15" S2P_D-3.8x2.4x1-PX4.7+15 174.5,102.5 r0 top
D207 "S2P_D-3.8x2.4x1-PX4.7+16" S2P_D-3.8x2.4x1-PX4.7+16 181.5,102.5 r0 top
D208 "S2P_D-3.8x2.4x1-PX4.7+17" S2P_D-3.8x2.4x1-PX4.7+17 188.5,102.5 r0 top
D211 "_1SS403_+6" _1SS403_+6 276,101.25 r270 bottom
D212 "_1SS403_+7" _1SS403_+7 278.5,101.25 r270 bottom
D213 "_1SS403_+8" _1SS403_+8 281.25,101.25 r270 bottom
D217 "_1SS403_+19" _1SS403_+19 266.5,114.5 r270 bottom
D218 "_1SS403_+20" _1SS403_+20 281,115.75 r180 bottom
D219 "S2P_ZD-0.8x1.2x0.6-PY1.6+4" S2P_ZD-0.8x1.2x0.6-PY1.6+4 275.75,118.75 r180 bottom
D220 "_1SS403_+21" _1SS403_+21 273.5,118.75 r90 bottom
D221 "S2P_ZD-0.8x1.2x0.6-PY1.6+5" S2P_ZD-0.8x1.2x0.6-PY1.6+5 276.75,115.75 r90 bottom
D302 "S2P_D-3.8x2.4x1-PX4.7+18" S2P_D-3.8x2.4x1-PX4.7+18 175.25,70.5 r0 top
D303 "S2P_D-3.8x2.4x1-PX4.7+19" S2P_D-3.8x2.4x1-PX4.7+19 183,70.5 r0 top
D304 "S2P_D-3.8x2.4x1-PX4.7+20" S2P_D-3.8x2.4x1-PX4.7+20 190.75,70.5 r0 top
D305 "S2P_D-4.32x2.6x2.2-PX5.21+3" S2P_D-4.32x2.6x2.2-PX5.21+3 198.75,72.5 r180 top
D306 "S2P_D-3.8x2.4x1-PX4.7+21" S2P_D-3.8x2.4x1-PX4.7+21 174.5,42.5 r0 top
D307 "S2P_D-3.8x2.4x1-PX4.7+22" S2P_D-3.8x2.4x1-PX4.7+22 181.5,42.5 r0 top
D308 "S2P_D-3.8x2.4x1-PX4.7+23" S2P_D-3.8x2.4x1-PX4.7+23 188.5,42.5 r0 top
D311 "_1SS403_+9" _1SS403_+9 276,41.25 r270 bottom
D312 "_1SS403_+10" _1SS403_+10 278.5,41.25 r270 bottom
D313 "_1SS403_+11" _1SS403_+11 281.25,41.25 r270 bottom
D317 "_1SS403_+22" _1SS403_+22 266.5,54.5 r270 bottom
D318 "_1SS403_+23" _1SS403_+23 281,55.75 r180 bottom
D319 "S2P_ZD-0.8x1.2x0.6-PY1.6+6" S2P_ZD-0.8x1.2x0.6-PY1.6+6 275.75,58.75 r180 bottom
D320 "_1SS403_+12" _1SS403_+12 273.5,58.75 r90 bottom
D321 "S2P_ZD-0.8x1.2x0.6-PY1.6+7" S2P_ZD-0.8x1.2x0.6-PY1.6+7 276.75,55.75 r90 bottom
D322 "1SS403E" 1SS403E 54.925,242.727 r0 top
D323 "1SS403E" 1SS403E 54.925,182.72 r0 top
D324 "1SS403E" 1SS403E 54.925,122.712 r0 top
D325 "1SS403E" 1SS403E 54.925,62.705 r0 top
IC1 "_LTC4364HMS-2#PBF_" _LTC4364HMS-2#PBF_ 62.75,238.5 r270 top
IC2 "S9P_U-4.9x3.9x1.7-PX1.27-PY6" S9P_U-4.9x3.9x1.7-PX1.27-PY6 198,237.25 r180 top
IC11 "S8P_U-4.4x3x1.2-PX6.4-PY0.65" S8P_U-4.4x3x1.2-PX6.4-PY0.65 118.25,211 r0 bottom
IC12 "S16P_U-5x4.4x1.2-PX0.65-PY6.4" S16P_U-5x4.4x1.2-PX0.65-PY6.4 271.75,228 r0 bottom
IC13 "_TC7PZ17FU_" _TC7PZ17FU_ 191.25,215.75 r270 top
IC14 "S8P_U-4.9x3.9x1.75-PX1.27-PY6" S8P_U-4.9x3.9x1.75-PX1.27-PY6 185,215.75 r270 top
IC101 "_LTC4364HMS-2#PBF_+1" _LTC4364HMS-2#PBF_+1 62.75,178.5 r270 top
IC102 "S9P_U-4.9x3.9x1.7-PX1.27-PY6+1" S9P_U-4.9x3.9x1.7-PX1.27-PY6+1 198,177.25 r180 top
IC111 "S8P_U-4.4x3x1.2-PX6.4-PY0.65+1" S8P_U-4.4x3x1.2-PX6.4-PY0.65+1 118.25,151 r0 bottom
IC112 "S16P_U-5x4.4x1.2-PX0.65-PY6.4+1" S16P_U-5x4.4x1.2-PX0.65-PY6.4+1 271.75,168 r0 bottom
IC113 "_TC7PZ17FU_+1" _TC7PZ17FU_+1 191.25,155.75 r270 top
IC114 "S8P_U-4.9x3.9x1.75-PX1.27-PY6+1" S8P_U-4.9x3.9x1.75-PX1.27-PY6+1 185,155.75 r270 top
IC201 "_LTC4364HMS-2#PBF_+2" _LTC4364HMS-2#PBF_+2 62.75,118.5 r270 top
IC202 "S9P_U-4.9x3.9x1.7-PX1.27-PY6+2" S9P_U-4.9x3.9x1.7-PX1.27-PY6+2 198,117.25 r180 top
IC211 "S8P_U-4.4x3x1.2-PX6.4-PY0.65+2" S8P_U-4.4x3x1.2-PX6.4-PY0.65+2 118.25,91 r0 bottom
IC212 "S16P_U-5x4.4x1.2-PX0.65-PY6.4+2" S16P_U-5x4.4x1.2-PX0.65-PY6.4+2 271.75,108 r0 bottom
IC213 "_TC7PZ17FU_+2" _TC7PZ17FU_+2 191.25,95.75 r270 top
IC214 "S8P_U-4.9x3.9x1.75-PX1.27-PY6+2" S8P_U-4.9x3.9x1.75-PX1.27-PY6+2 185,95.75 r270 top
IC301 "_LTC4364HMS-2#PBF_+3" _LTC4364HMS-2#PBF_+3 62.75,58.5 r270 top
IC302 "S9P_U-4.9x3.9x1.7-PX1.27-PY6+3" S9P_U-4.9x3.9x1.7-PX1.27-PY6+3 198,57.25 r180 top
IC311 "S8P_U-4.4x3x1.2-PX6.4-PY0.65+3" S8P_U-4.4x3x1.2-PX6.4-PY0.65+3 118.25,31 r0 bottom
IC312 "S16P_U-5x4.4x1.2-PX0.65-PY6.4+3" S16P_U-5x4.4x1.2-PX0.65-PY6.4+3 271.75,48 r0 bottom
IC313 "_TC7PZ17FU_+3" _TC7PZ17FU_+3 191.25,35.75 r270 top
IC314 "S8P_U-4.9x3.9x1.75-PX1.27-PY6+3" S8P_U-4.9x3.9x1.75-PX1.27-PY6+3 185,35.75 r270 top
L1 "_XAL1580-401MED_" _XAL1580-401MED_ 80.5,249 r90 top
L2 "D2P_L-38.1x21.9x39.4-PX21.33-PY10.87-H7x3" D2P_L-38.1x21.9x39.4-PX21.33-PY10.87-H7x3 214,240 r270 top
L101 "_XAL1580-401MED_+1" _XAL1580-401MED_+1 80.5,189 r90 top
L102 "D2P_L-38.1x21.9x39.4-PX21.33-PY10.87-H7x3" D2P_L-38.1x21.9x39.4-PX21.33-PY10.87-H7x3 214,180 r270 top
L201 "_XAL1580-401MED_+2" _XAL1580-401MED_+2 80.5,129 r90 top
L202 "D2P_L-38.1x21.9x39.4-PX21.33-PY10.87-H7x3" D2P_L-38.1x21.9x39.4-PX21.33-PY10.87-H7x3 214,120 r270 top
L301 "_XAL1580-401MED_+3" _XAL1580-401MED_+3 80.5,69 r90 top
L302 "D2P_L-38.1x21.9x39.4-PX21.33-PY10.87-H7x3" D2P_L-38.1x21.9x39.4-PX21.33-PY10.87-H7x3 214,60 r270 top
PC1 "S4P_PC-3.7?4.55?2.1-PX2.54-PY7" S4P_PC-3.7?4.55?2.1-PX2.54-PY7 96,214.25 r0 bottom
PC2 "S4P_PC-2.6x4.55?2.1-PX1.27-PY7" S4P_PC-2.6x4.55?2.1-PX1.27-PY7 91.5,214.25 r180 bottom
PC3 "S4P_PC-3.7?4.55?2.1-PX2.54-PY7+1" S4P_PC-3.7?4.55?2.1-PX2.54-PY7+1 101,214.25 r0 bottom
PC4 "S4P_PC-3.7?4.55?2.1-PX2.54-PY7+2" S4P_PC-3.7?4.55?2.1-PX2.54-PY7+2 106,214.25 r0 bottom
PC5 "S4P_PC-2.6x4.55?2.1-PX1.27-PY7+1" S4P_PC-2.6x4.55?2.1-PX1.27-PY7+1 278.5,214 r0 bottom
PC6 "S4P_PC-2.6x4.55?2.1-PX1.27-PY7+2" S4P_PC-2.6x4.55?2.1-PX1.27-PY7+2 270.5,214 r0 bottom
